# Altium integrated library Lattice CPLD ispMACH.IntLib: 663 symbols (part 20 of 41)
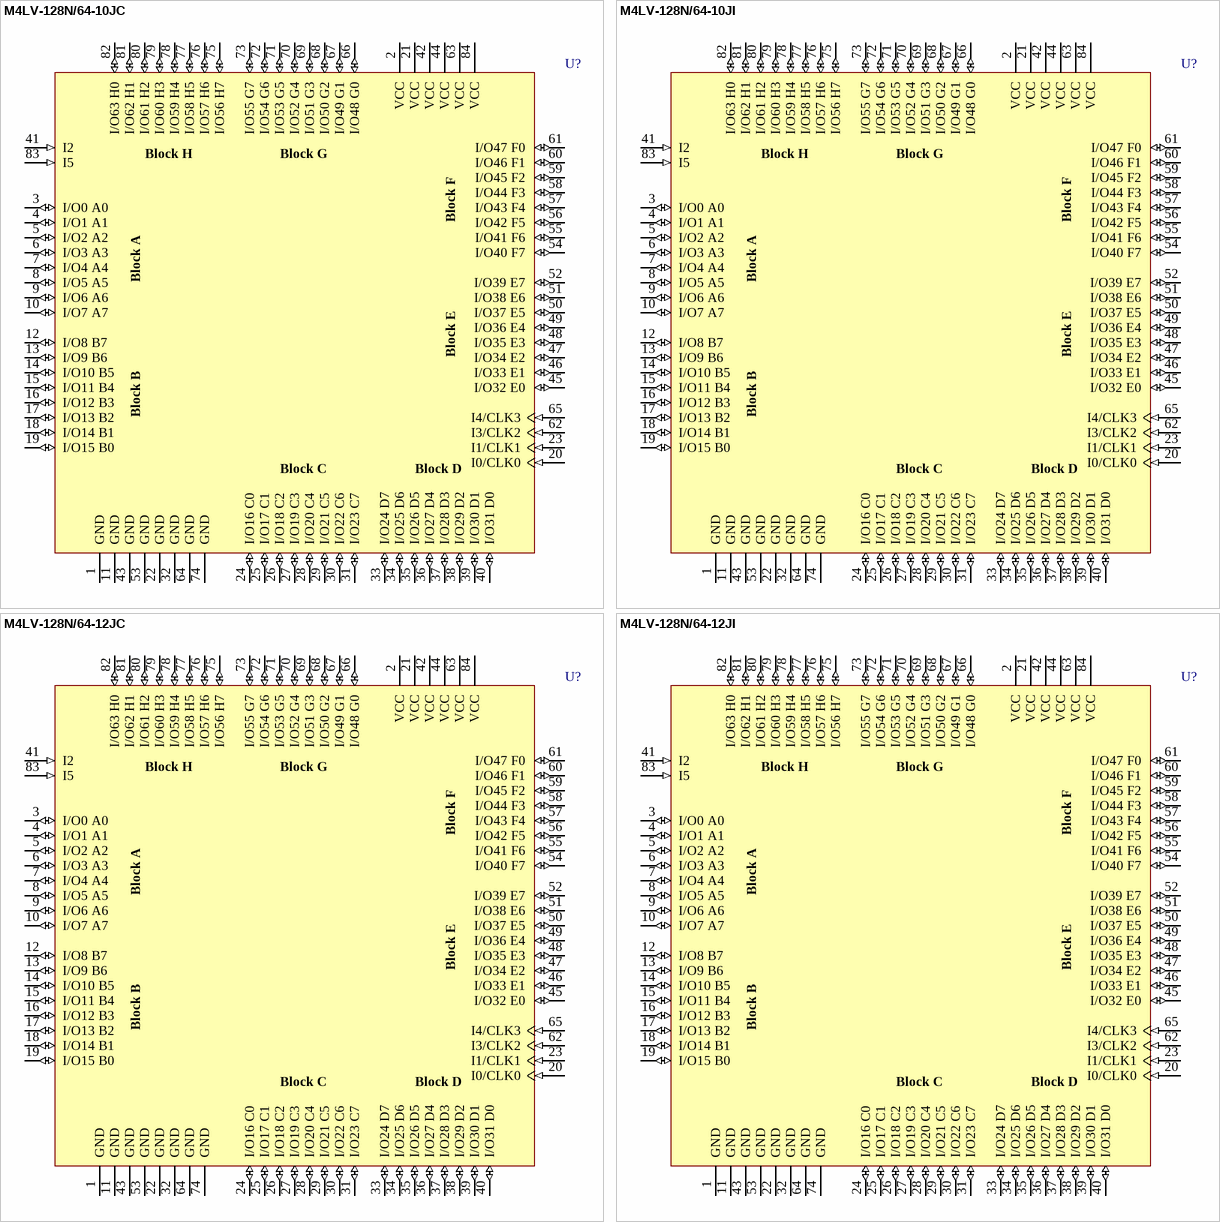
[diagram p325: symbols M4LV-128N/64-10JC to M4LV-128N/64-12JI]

## M4LV-128N/64-10JI
designator U?
High-Performance EE CMOS In-System Programmable Logic
footprint PLCC84_N (Leaded Chip Carrier, 84-Leads, Body 29.3x29.3mm, Pitch 1.27mm, IPC Medium Density)
footprint PLCC84_L (Leaded Chip Carrier, 84-Leads, Body 29.3x29.3mm, Pitch 1.27mm, IPC High Density)
footprint PLCC84_M (Leaded Chip Carrier, 84-Leads, Body 29.3x29.3mm, Pitch 1.27mm, IPC Low Density)
3D model M4LV-PLCC84 (84-Pin Leaded Chip Carrier 1.27 mm Pitch)
pins: 1 GND (power), 2 VCC (power), 3 I/O0 A0 (io), 4 I/O1 A1 (io), 5 I/O2 A2 (io), 6 I/O3 A3 (io), 7 I/O4 A4 (io), 8 I/O5 A5 (io), 9 I/O6 A6 (io), 10 I/O7 A7 (io), 11 GND (power), 12 I/O8 B7 (io), 13 I/O9 B6 (io), 14 I/O10 B5 (io), 15 I/O11 B4 (io), 16 I/O12 B3 (io), 17 I/O13 B2 (io), 18 I/O14 B1 (io), 19 I/O15 B0 (io), 20 I0/CLK0 (in), 21 VCC (power), 22 GND (power), 23 I1/CLK1 (in), 24 I/O16 C0 (io), 25 I/O17 C1 (io), 26 I/O18 C2 (io), 27 I/O19 C3 (io), 28 I/O20 C4 (io), 29 I/O21 C5 (io), 30 I/O22 C6 (io), 31 I/O23 C7 (io), 32 GND (power), 33 I/O24 D7 (io), 34 I/O25 D6 (io), 35 I/O26 D5 (io), 36 I/O27 D4 (io), 37 I/O28 D3 (io), 38 I/O29 D2 (io), 39 I/O30 D1 (io), 40 I/O31 D0 (io), 41 I2 (in), 42 VCC (power), 43 GND (power), 44 VCC (power), 45 I/O32 E0 (io), 46 I/O33 E1 (io), 47 I/O34 E2 (io), 48 I/O35 E3 (io), 49 I/O36 E4 (io), 50 I/O37 E5 (io), 51 I/O38 E6 (io), 52 I/O39 E7 (io), 53 GND (power), 54 I/O40 F7 (io), 55 I/O41 F6 (io), 56 I/O42 F5 (io), 57 I/O43 F4 (io), 58 I/O44 F3 (io), 59 I/O45 F2 (io), 60 I/O46 F1 (io), 61 I/O47 F0 (io), 62 I3/CLK2 (in), 63 VCC (power), 64 GND (power), 65 I4/CLK3 (in), 66 I/O48 G0 (io), 67 I/O49 G1 (io), 68 I/O50 G2 (io), 69 I/O51 G3 (io), 70 I/O52 G4 (io), 71 I/O53 G5 (io), 72 I/O54 G6 (io), 73 I/O55 G7 (io), 74 GND (power), 75 I/O56 H7 (io), 76 I/O57 H6 (io), 77 I/O58 H5 (io), 78 I/O59 H4 (io), 79 I/O60 H3 (io), 80 I/O61 H2 (io), 81 I/O62 H1 (io), 82 I/O63 H0 (io), 83 I5 (in), 84 VCC (power)

## M4LV-128N/64-12JC
designator U?
High-Performance EE CMOS In-System Programmable Logic
footprint PLCC84_N (Leaded Chip Carrier, 84-Leads, Body 29.3x29.3mm, Pitch 1.27mm, IPC Medium Density)
footprint PLCC84_L (Leaded Chip Carrier, 84-Leads, Body 29.3x29.3mm, Pitch 1.27mm, IPC High Density)
footprint PLCC84_M (Leaded Chip Carrier, 84-Leads, Body 29.3x29.3mm, Pitch 1.27mm, IPC Low Density)
3D model M4LV-PLCC84 (84-Pin Leaded Chip Carrier 1.27 mm Pitch)
pins: 1 GND (power), 2 VCC (power), 3 I/O0 A0 (io), 4 I/O1 A1 (io), 5 I/O2 A2 (io), 6 I/O3 A3 (io), 7 I/O4 A4 (io), 8 I/O5 A5 (io), 9 I/O6 A6 (io), 10 I/O7 A7 (io), 11 GND (power), 12 I/O8 B7 (io), 13 I/O9 B6 (io), 14 I/O10 B5 (io), 15 I/O11 B4 (io), 16 I/O12 B3 (io), 17 I/O13 B2 (io), 18 I/O14 B1 (io), 19 I/O15 B0 (io), 20 I0/CLK0 (in), 21 VCC (power), 22 GND (power), 23 I1/CLK1 (in), 24 I/O16 C0 (io), 25 I/O17 C1 (io), 26 I/O18 C2 (io), 27 I/O19 C3 (io), 28 I/O20 C4 (io), 29 I/O21 C5 (io), 30 I/O22 C6 (io), 31 I/O23 C7 (io), 32 GND (power), 33 I/O24 D7 (io), 34 I/O25 D6 (io), 35 I/O26 D5 (io), 36 I/O27 D4 (io), 37 I/O28 D3 (io), 38 I/O29 D2 (io), 39 I/O30 D1 (io), 40 I/O31 D0 (io), 41 I2 (in), 42 VCC (power), 43 GND (power), 44 VCC (power), 45 I/O32 E0 (io), 46 I/O33 E1 (io), 47 I/O34 E2 (io), 48 I/O35 E3 (io), 49 I/O36 E4 (io), 50 I/O37 E5 (io), 51 I/O38 E6 (io), 52 I/O39 E7 (io), 53 GND (power), 54 I/O40 F7 (io), 55 I/O41 F6 (io), 56 I/O42 F5 (io), 57 I/O43 F4 (io), 58 I/O44 F3 (io), 59 I/O45 F2 (io), 60 I/O46 F1 (io), 61 I/O47 F0 (io), 62 I3/CLK2 (in), 63 VCC (power), 64 GND (power), 65 I4/CLK3 (in), 66 I/O48 G0 (io), 67 I/O49 G1 (io), 68 I/O50 G2 (io), 69 I/O51 G3 (io), 70 I/O52 G4 (io), 71 I/O53 G5 (io), 72 I/O54 G6 (io), 73 I/O55 G7 (io), 74 GND (power), 75 I/O56 H7 (io), 76 I/O57 H6 (io), 77 I/O58 H5 (io), 78 I/O59 H4 (io), 79 I/O60 H3 (io), 80 I/O61 H2 (io), 81 I/O62 H1 (io), 82 I/O63 H0 (io), 83 I5 (in), 84 VCC (power)

## M4LV-128N/64-12JI
designator U?
High-Performance EE CMOS In-System Programmable Logic
footprint PLCC84_N (Leaded Chip Carrier, 84-Leads, Body 29.3x29.3mm, Pitch 1.27mm, IPC Medium Density)
footprint PLCC84_L (Leaded Chip Carrier, 84-Leads, Body 29.3x29.3mm, Pitch 1.27mm, IPC High Density)
footprint PLCC84_M (Leaded Chip Carrier, 84-Leads, Body 29.3x29.3mm, Pitch 1.27mm, IPC Low Density)
3D model M4LV-PLCC84 (84-Pin Leaded Chip Carrier 1.27 mm Pitch)
pins: 1 GND (power), 2 VCC (power), 3 I/O0 A0 (io), 4 I/O1 A1 (io), 5 I/O2 A2 (io), 6 I/O3 A3 (io), 7 I/O4 A4 (io), 8 I/O5 A5 (io), 9 I/O6 A6 (io), 10 I/O7 A7 (io), 11 GND (power), 12 I/O8 B7 (io), 13 I/O9 B6 (io), 14 I/O10 B5 (io), 15 I/O11 B4 (io), 16 I/O12 B3 (io), 17 I/O13 B2 (io), 18 I/O14 B1 (io), 19 I/O15 B0 (io), 20 I0/CLK0 (in), 21 VCC (power), 22 GND (power), 23 I1/CLK1 (in), 24 I/O16 C0 (io), 25 I/O17 C1 (io), 26 I/O18 C2 (io), 27 I/O19 C3 (io), 28 I/O20 C4 (io), 29 I/O21 C5 (io), 30 I/O22 C6 (io), 31 I/O23 C7 (io), 32 GND (power), 33 I/O24 D7 (io), 34 I/O25 D6 (io), 35 I/O26 D5 (io), 36 I/O27 D4 (io), 37 I/O28 D3 (io), 38 I/O29 D2 (io), 39 I/O30 D1 (io), 40 I/O31 D0 (io), 41 I2 (in), 42 VCC (power), 43 GND (power), 44 VCC (power), 45 I/O32 E0 (io), 46 I/O33 E1 (io), 47 I/O34 E2 (io), 48 I/O35 E3 (io), 49 I/O36 E4 (io), 50 I/O37 E5 (io), 51 I/O38 E6 (io), 52 I/O39 E7 (io), 53 GND (power), 54 I/O40 F7 (io), 55 I/O41 F6 (io), 56 I/O42 F5 (io), 57 I/O43 F4 (io), 58 I/O44 F3 (io), 59 I/O45 F2 (io), 60 I/O46 F1 (io), 61 I/O47 F0 (io), 62 I3/CLK2 (in), 63 VCC (power), 64 GND (power), 65 I4/CLK3 (in), 66 I/O48 G0 (io), 67 I/O49 G1 (io), 68 I/O50 G2 (io), 69 I/O51 G3 (io), 70 I/O52 G4 (io), 71 I/O53 G5 (io), 72 I/O54 G6 (io), 73 I/O55 G7 (io), 74 GND (power), 75 I/O56 H7 (io), 76 I/O57 H6 (io), 77 I/O58 H5 (io), 78 I/O59 H4 (io), 79 I/O60 H3 (io), 80 I/O61 H2 (io), 81 I/O62 H1 (io), 82 I/O63 H0 (io), 83 I5 (in), 84 VCC (power)

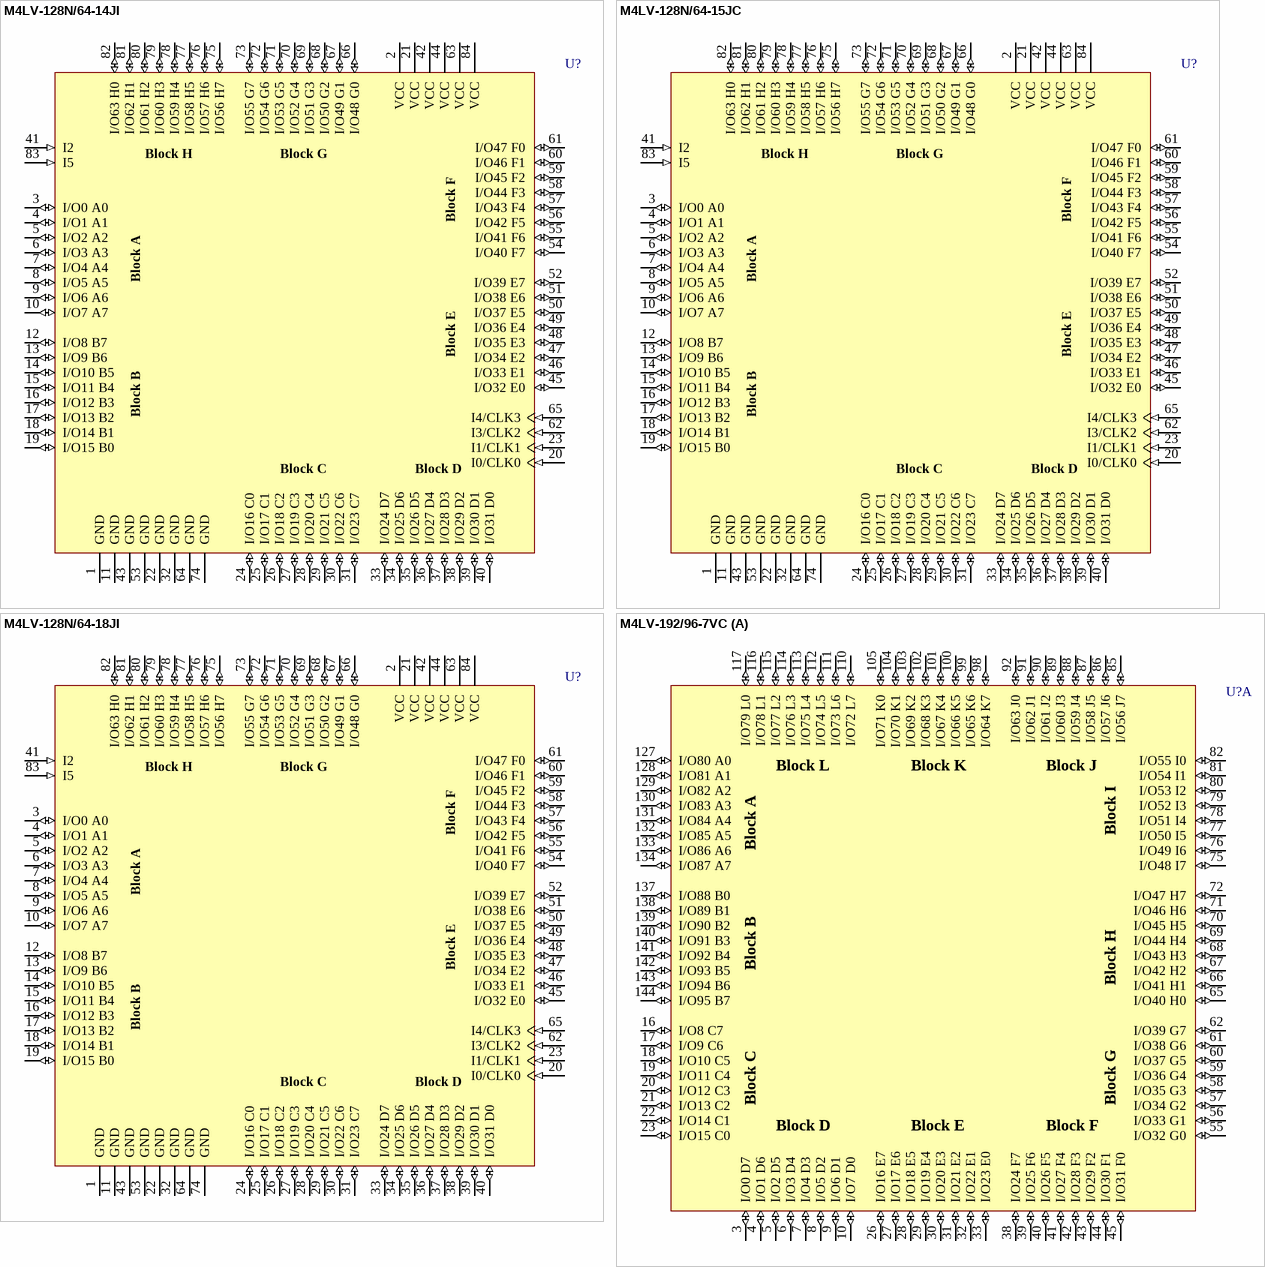
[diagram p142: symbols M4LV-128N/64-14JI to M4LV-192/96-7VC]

## M4LV-128N/64-14JI
designator U?
High-Performance EE CMOS In-System Programmable Logic
footprint PLCC84_N (Leaded Chip Carrier, 84-Leads, Body 29.3x29.3mm, Pitch 1.27mm, IPC Medium Density)
footprint PLCC84_L (Leaded Chip Carrier, 84-Leads, Body 29.3x29.3mm, Pitch 1.27mm, IPC High Density)
footprint PLCC84_M (Leaded Chip Carrier, 84-Leads, Body 29.3x29.3mm, Pitch 1.27mm, IPC Low Density)
3D model M4LV-PLCC84 (84-Pin Leaded Chip Carrier 1.27 mm Pitch)
pins: 1 GND (power), 2 VCC (power), 3 I/O0 A0 (io), 4 I/O1 A1 (io), 5 I/O2 A2 (io), 6 I/O3 A3 (io), 7 I/O4 A4 (io), 8 I/O5 A5 (io), 9 I/O6 A6 (io), 10 I/O7 A7 (io), 11 GND (power), 12 I/O8 B7 (io), 13 I/O9 B6 (io), 14 I/O10 B5 (io), 15 I/O11 B4 (io), 16 I/O12 B3 (io), 17 I/O13 B2 (io), 18 I/O14 B1 (io), 19 I/O15 B0 (io), 20 I0/CLK0 (in), 21 VCC (power), 22 GND (power), 23 I1/CLK1 (in), 24 I/O16 C0 (io), 25 I/O17 C1 (io), 26 I/O18 C2 (io), 27 I/O19 C3 (io), 28 I/O20 C4 (io), 29 I/O21 C5 (io), 30 I/O22 C6 (io), 31 I/O23 C7 (io), 32 GND (power), 33 I/O24 D7 (io), 34 I/O25 D6 (io), 35 I/O26 D5 (io), 36 I/O27 D4 (io), 37 I/O28 D3 (io), 38 I/O29 D2 (io), 39 I/O30 D1 (io), 40 I/O31 D0 (io), 41 I2 (in), 42 VCC (power), 43 GND (power), 44 VCC (power), 45 I/O32 E0 (io), 46 I/O33 E1 (io), 47 I/O34 E2 (io), 48 I/O35 E3 (io), 49 I/O36 E4 (io), 50 I/O37 E5 (io), 51 I/O38 E6 (io), 52 I/O39 E7 (io), 53 GND (power), 54 I/O40 F7 (io), 55 I/O41 F6 (io), 56 I/O42 F5 (io), 57 I/O43 F4 (io), 58 I/O44 F3 (io), 59 I/O45 F2 (io), 60 I/O46 F1 (io), 61 I/O47 F0 (io), 62 I3/CLK2 (in), 63 VCC (power), 64 GND (power), 65 I4/CLK3 (in), 66 I/O48 G0 (io), 67 I/O49 G1 (io), 68 I/O50 G2 (io), 69 I/O51 G3 (io), 70 I/O52 G4 (io), 71 I/O53 G5 (io), 72 I/O54 G6 (io), 73 I/O55 G7 (io), 74 GND (power), 75 I/O56 H7 (io), 76 I/O57 H6 (io), 77 I/O58 H5 (io), 78 I/O59 H4 (io), 79 I/O60 H3 (io), 80 I/O61 H2 (io), 81 I/O62 H1 (io), 82 I/O63 H0 (io), 83 I5 (in), 84 VCC (power)

## M4LV-128N/64-15JC
designator U?
High-Performance EE CMOS In-System Programmable Logic
footprint PLCC84_N (Leaded Chip Carrier, 84-Leads, Body 29.3x29.3mm, Pitch 1.27mm, IPC Medium Density)
footprint PLCC84_L (Leaded Chip Carrier, 84-Leads, Body 29.3x29.3mm, Pitch 1.27mm, IPC High Density)
footprint PLCC84_M (Leaded Chip Carrier, 84-Leads, Body 29.3x29.3mm, Pitch 1.27mm, IPC Low Density)
3D model M4LV-PLCC84 (84-Pin Leaded Chip Carrier 1.27 mm Pitch)
pins: 1 GND (power), 2 VCC (power), 3 I/O0 A0 (io), 4 I/O1 A1 (io), 5 I/O2 A2 (io), 6 I/O3 A3 (io), 7 I/O4 A4 (io), 8 I/O5 A5 (io), 9 I/O6 A6 (io), 10 I/O7 A7 (io), 11 GND (power), 12 I/O8 B7 (io), 13 I/O9 B6 (io), 14 I/O10 B5 (io), 15 I/O11 B4 (io), 16 I/O12 B3 (io), 17 I/O13 B2 (io), 18 I/O14 B1 (io), 19 I/O15 B0 (io), 20 I0/CLK0 (in), 21 VCC (power), 22 GND (power), 23 I1/CLK1 (in), 24 I/O16 C0 (io), 25 I/O17 C1 (io), 26 I/O18 C2 (io), 27 I/O19 C3 (io), 28 I/O20 C4 (io), 29 I/O21 C5 (io), 30 I/O22 C6 (io), 31 I/O23 C7 (io), 32 GND (power), 33 I/O24 D7 (io), 34 I/O25 D6 (io), 35 I/O26 D5 (io), 36 I/O27 D4 (io), 37 I/O28 D3 (io), 38 I/O29 D2 (io), 39 I/O30 D1 (io), 40 I/O31 D0 (io), 41 I2 (in), 42 VCC (power), 43 GND (power), 44 VCC (power), 45 I/O32 E0 (io), 46 I/O33 E1 (io), 47 I/O34 E2 (io), 48 I/O35 E3 (io), 49 I/O36 E4 (io), 50 I/O37 E5 (io), 51 I/O38 E6 (io), 52 I/O39 E7 (io), 53 GND (power), 54 I/O40 F7 (io), 55 I/O41 F6 (io), 56 I/O42 F5 (io), 57 I/O43 F4 (io), 58 I/O44 F3 (io), 59 I/O45 F2 (io), 60 I/O46 F1 (io), 61 I/O47 F0 (io), 62 I3/CLK2 (in), 63 VCC (power), 64 GND (power), 65 I4/CLK3 (in), 66 I/O48 G0 (io), 67 I/O49 G1 (io), 68 I/O50 G2 (io), 69 I/O51 G3 (io), 70 I/O52 G4 (io), 71 I/O53 G5 (io), 72 I/O54 G6 (io), 73 I/O55 G7 (io), 74 GND (power), 75 I/O56 H7 (io), 76 I/O57 H6 (io), 77 I/O58 H5 (io), 78 I/O59 H4 (io), 79 I/O60 H3 (io), 80 I/O61 H2 (io), 81 I/O62 H1 (io), 82 I/O63 H0 (io), 83 I5 (in), 84 VCC (power)

## M4LV-128N/64-18JI
designator U?
High-Performance EE CMOS In-System Programmable Logic
footprint PLCC84_N (Leaded Chip Carrier, 84-Leads, Body 29.3x29.3mm, Pitch 1.27mm, IPC Medium Density)
footprint PLCC84_L (Leaded Chip Carrier, 84-Leads, Body 29.3x29.3mm, Pitch 1.27mm, IPC High Density)
footprint PLCC84_M (Leaded Chip Carrier, 84-Leads, Body 29.3x29.3mm, Pitch 1.27mm, IPC Low Density)
3D model M4LV-PLCC84 (84-Pin Leaded Chip Carrier 1.27 mm Pitch)
pins: 1 GND (power), 2 VCC (power), 3 I/O0 A0 (io), 4 I/O1 A1 (io), 5 I/O2 A2 (io), 6 I/O3 A3 (io), 7 I/O4 A4 (io), 8 I/O5 A5 (io), 9 I/O6 A6 (io), 10 I/O7 A7 (io), 11 GND (power), 12 I/O8 B7 (io), 13 I/O9 B6 (io), 14 I/O10 B5 (io), 15 I/O11 B4 (io), 16 I/O12 B3 (io), 17 I/O13 B2 (io), 18 I/O14 B1 (io), 19 I/O15 B0 (io), 20 I0/CLK0 (in), 21 VCC (power), 22 GND (power), 23 I1/CLK1 (in), 24 I/O16 C0 (io), 25 I/O17 C1 (io), 26 I/O18 C2 (io), 27 I/O19 C3 (io), 28 I/O20 C4 (io), 29 I/O21 C5 (io), 30 I/O22 C6 (io), 31 I/O23 C7 (io), 32 GND (power), 33 I/O24 D7 (io), 34 I/O25 D6 (io), 35 I/O26 D5 (io), 36 I/O27 D4 (io), 37 I/O28 D3 (io), 38 I/O29 D2 (io), 39 I/O30 D1 (io), 40 I/O31 D0 (io), 41 I2 (in), 42 VCC (power), 43 GND (power), 44 VCC (power), 45 I/O32 E0 (io), 46 I/O33 E1 (io), 47 I/O34 E2 (io), 48 I/O35 E3 (io), 49 I/O36 E4 (io), 50 I/O37 E5 (io), 51 I/O38 E6 (io), 52 I/O39 E7 (io), 53 GND (power), 54 I/O40 F7 (io), 55 I/O41 F6 (io), 56 I/O42 F5 (io), 57 I/O43 F4 (io), 58 I/O44 F3 (io), 59 I/O45 F2 (io), 60 I/O46 F1 (io), 61 I/O47 F0 (io), 62 I3/CLK2 (in), 63 VCC (power), 64 GND (power), 65 I4/CLK3 (in), 66 I/O48 G0 (io), 67 I/O49 G1 (io), 68 I/O50 G2 (io), 69 I/O51 G3 (io), 70 I/O52 G4 (io), 71 I/O53 G5 (io), 72 I/O54 G6 (io), 73 I/O55 G7 (io), 74 GND (power), 75 I/O56 H7 (io), 76 I/O57 H6 (io), 77 I/O58 H5 (io), 78 I/O59 H4 (io), 79 I/O60 H3 (io), 80 I/O61 H2 (io), 81 I/O62 H1 (io), 82 I/O63 H0 (io), 83 I5 (in), 84 VCC (power)

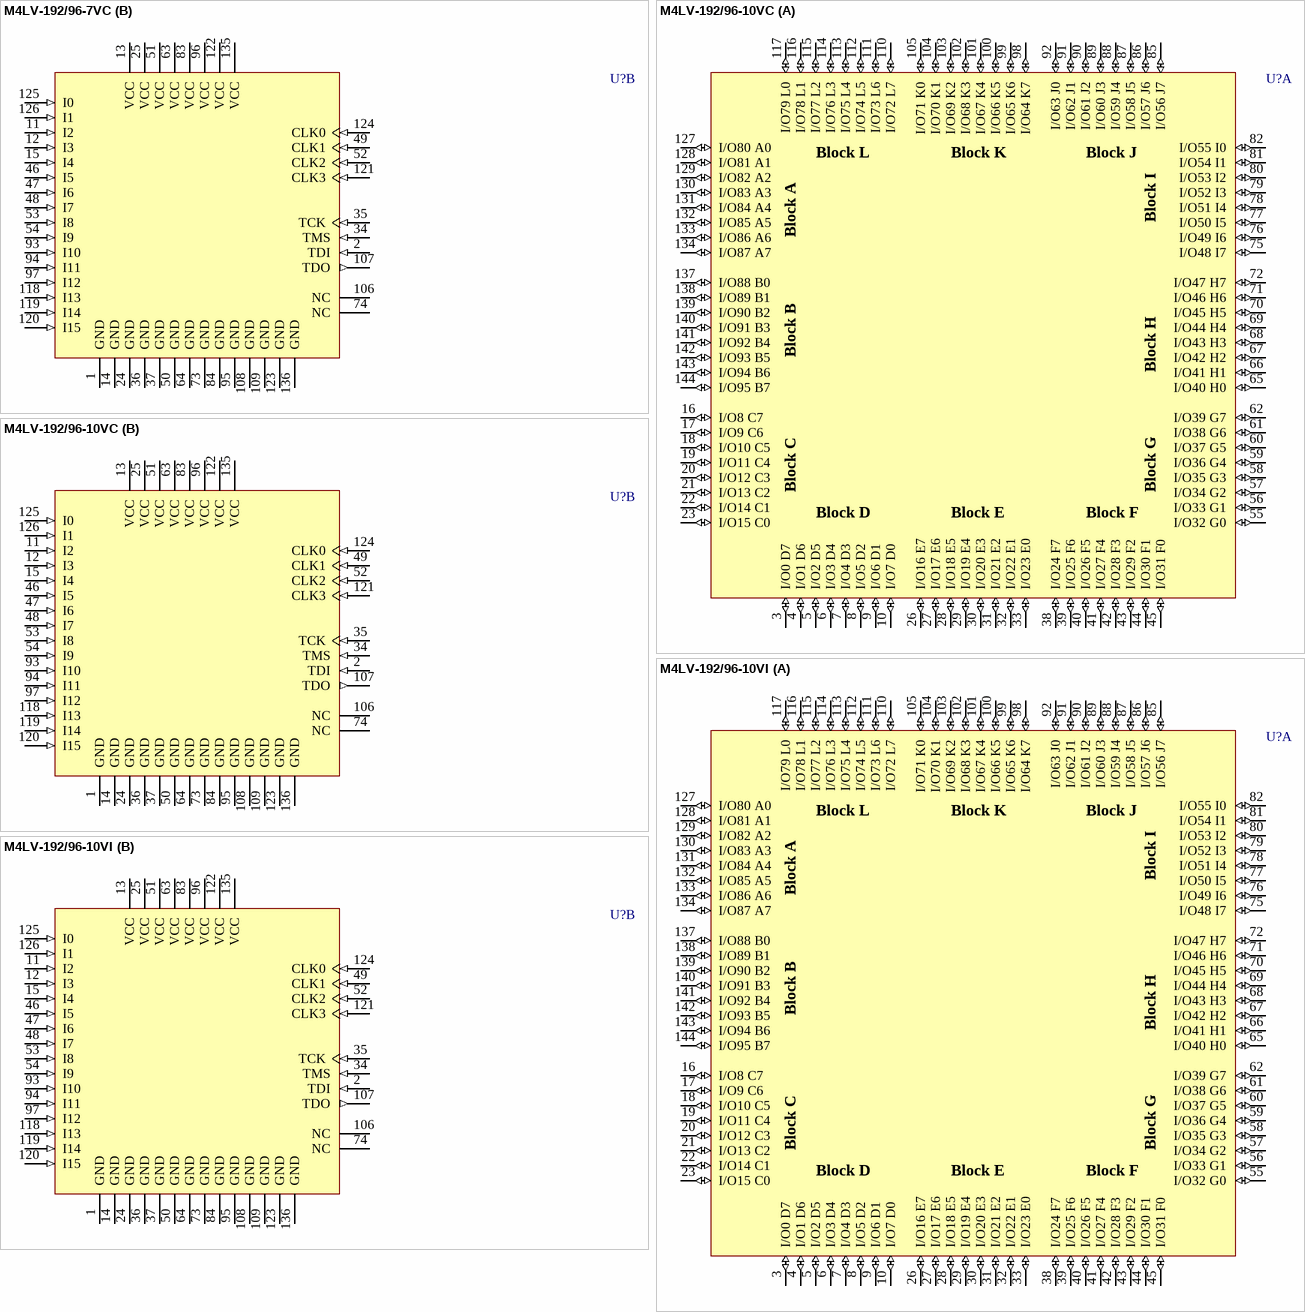
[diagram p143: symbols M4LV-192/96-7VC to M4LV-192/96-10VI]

## M4LV-192/96-7VC
designator U?
High-Performance EE CMOS In-System Programmable Logic
footprint TQFP144_N (Thin QFP, 144-Leads, Body 20x20mm, Pitch 0.5mm, IPC Medium Density)
footprint TQFP144_L (Thin QFP, 144-Leads, Body 20x20mm, Pitch 0.5mm, IPC High Density)
footprint TQFP144_M (Thin QFP, 144-Leads, Body 20x20mm, Pitch 0.5mm, IPC Low Density)
3D model M4LV-TQFP144 (144-Pin Thin Quad Flat Pack (TQFP144))
part A pins: 3 I/O0 D7 (io), 4 I/O1 D6 (io), 5 I/O2 D5 (io), 6 I/O3 D4 (io), 7 I/O4 D3 (io), 8 I/O5 D2 (io), 9 I/O6 D1 (io), 10 I/O7 D0 (io), 16 I/O8 C7 (io), 17 I/O9 C6 (io), 18 I/O10 C5 (io), 19 I/O11 C4 (io), 20 I/O12 C3 (io), 21 I/O13 C2 (io), 22 I/O14 C1 (io), 23 I/O15 C0 (io), 26 I/O16 E7 (io), 27 I/O17 E6 (io), 28 I/O18 E5 (io), 29 I/O19 E4 (io), 30 I/O20 E3 (io), 31 I/O21 E2 (io), 32 I/O22 E1 (io), 33 I/O23 E0 (io), 38 I/O24 F7 (io), 39 I/O25 F6 (io), 40 I/O26 F5 (io), 41 I/O27 F4 (io), 42 I/O28 F3 (io), 43 I/O29 F2 (io), 44 I/O30 F1 (io), 45 I/O31 F0 (io), 55 I/O32 G0 (io), 56 I/O33 G1 (io), 57 I/O34 G2 (io), 58 I/O35 G3 (io), 59 I/O36 G4 (io), 60 I/O37 G5 (io), 61 I/O38 G6 (io), 62 I/O39 G7 (io), 65 I/O40 H0 (io), 66 I/O41 H1 (io), 67 I/O42 H2 (io), 68 I/O43 H3 (io), 69 I/O44 H4 (io), 70 I/O45 H5 (io), 71 I/O46 H6 (io), 72 I/O47 H7 (io), 75 I/O48 I7 (io), 76 I/O49 I6 (io), 77 I/O50 I5 (io), 78 I/O51 I4 (io), 79 I/O52 I3 (io), 80 I/O53 I2 (io), 81 I/O54 I1 (io), 82 I/O55 I0 (io), 85 I/O56 J7 (io), 86 I/O57 J6 (io), 87 I/O58 J5 (io), 88 I/O59 J4 (io), 89 I/O60 J3 (io), 90 I/O61 J2 (io), 91 I/O62 J1 (io), 92 I/O63 J0 (io), 98 I/O64 K7 (io), 99 I/O65 K6 (io), 100 I/O66 K5 (io), 101 I/O67 K4 (io), 102 I/O68 K3 (io), 103 I/O69 K2 (io), 104 I/O70 K1 (io), 105 I/O71 K0 (io), 110 I/O72 L7 (io), 111 I/O73 L6 (io), 112 I/O74 L5 (io), 113 I/O75 L4 (io), 114 I/O76 L3 (io), 115 I/O77 L2 (io), 116 I/O78 L1 (io), 117 I/O79 L0 (io), 127 I/O80 A0 (io), 128 I/O81 A1 (io), 129 I/O82 A2 (io), 130 I/O83 A3 (io), 131 I/O84 A4 (io), 132 I/O85 A5 (io), 133 I/O86 A6 (io), 134 I/O87 A7 (io), 137 I/O88 B0 (io), 138 I/O89 B1 (io), 139 I/O90 B2 (io), 140 I/O91 B3 (io), 141 I/O92 B4 (io), 142 I/O93 B5 (io), 143 I/O94 B6 (io), 144 I/O95 B7 (io)
part B pins: 1 GND (power), 2 TDI (in), 11 I2 (in), 12 I3 (in), 13 VCC (power), 14 GND (power), 15 I4 (in), 24 GND (power), 25 VCC (power), 34 TMS (in), 35 TCK (in), 36 GND (power), 37 GND (power), 46 I5 (in), 47 I6 (in), 48 I7 (in), 49 CLK1 (in), 50 GND (power), 51 VCC (power), 52 CLK2 (in), 53 I8 (in), 54 I9 (in), 63 VCC (power), 64 GND (power), 73 GND (power), 74 NC, 83 VCC (power), 84 GND (power), 93 I10 (in), 94 I11 (in), 95 GND (power), 96 VCC (power), 97 I12 (in), 106 NC, 107 TDO (out), 108 GND (power), 109 GND (power), 118 I13 (in), 119 I14 (in), 120 I15 (in), 121 CLK3 (in), 122 VCC (power), 123 GND (power), 124 CLK0 (in), 125 I0 (in), 126 I1 (in), 135 VCC (power), 136 GND (power)

## M4LV-192/96-10VC
designator U?
High-Performance EE CMOS In-System Programmable Logic
footprint TQFP144_N (Thin QFP, 144-Leads, Body 20x20mm, Pitch 0.5mm, IPC Medium Density)
footprint TQFP144_L (Thin QFP, 144-Leads, Body 20x20mm, Pitch 0.5mm, IPC High Density)
footprint TQFP144_M (Thin QFP, 144-Leads, Body 20x20mm, Pitch 0.5mm, IPC Low Density)
3D model M4LV-TQFP144 (144-Pin Thin Quad Flat Pack (TQFP144))
part A pins: 3 I/O0 D7 (io), 4 I/O1 D6 (io), 5 I/O2 D5 (io), 6 I/O3 D4 (io), 7 I/O4 D3 (io), 8 I/O5 D2 (io), 9 I/O6 D1 (io), 10 I/O7 D0 (io), 16 I/O8 C7 (io), 17 I/O9 C6 (io), 18 I/O10 C5 (io), 19 I/O11 C4 (io), 20 I/O12 C3 (io), 21 I/O13 C2 (io), 22 I/O14 C1 (io), 23 I/O15 C0 (io), 26 I/O16 E7 (io), 27 I/O17 E6 (io), 28 I/O18 E5 (io), 29 I/O19 E4 (io), 30 I/O20 E3 (io), 31 I/O21 E2 (io), 32 I/O22 E1 (io), 33 I/O23 E0 (io), 38 I/O24 F7 (io), 39 I/O25 F6 (io), 40 I/O26 F5 (io), 41 I/O27 F4 (io), 42 I/O28 F3 (io), 43 I/O29 F2 (io), 44 I/O30 F1 (io), 45 I/O31 F0 (io), 55 I/O32 G0 (io), 56 I/O33 G1 (io), 57 I/O34 G2 (io), 58 I/O35 G3 (io), 59 I/O36 G4 (io), 60 I/O37 G5 (io), 61 I/O38 G6 (io), 62 I/O39 G7 (io), 65 I/O40 H0 (io), 66 I/O41 H1 (io), 67 I/O42 H2 (io), 68 I/O43 H3 (io), 69 I/O44 H4 (io), 70 I/O45 H5 (io), 71 I/O46 H6 (io), 72 I/O47 H7 (io), 75 I/O48 I7 (io), 76 I/O49 I6 (io), 77 I/O50 I5 (io), 78 I/O51 I4 (io), 79 I/O52 I3 (io), 80 I/O53 I2 (io), 81 I/O54 I1 (io), 82 I/O55 I0 (io), 85 I/O56 J7 (io), 86 I/O57 J6 (io), 87 I/O58 J5 (io), 88 I/O59 J4 (io), 89 I/O60 J3 (io), 90 I/O61 J2 (io), 91 I/O62 J1 (io), 92 I/O63 J0 (io), 98 I/O64 K7 (io), 99 I/O65 K6 (io), 100 I/O66 K5 (io), 101 I/O67 K4 (io), 102 I/O68 K3 (io), 103 I/O69 K2 (io), 104 I/O70 K1 (io), 105 I/O71 K0 (io), 110 I/O72 L7 (io), 111 I/O73 L6 (io), 112 I/O74 L5 (io), 113 I/O75 L4 (io), 114 I/O76 L3 (io), 115 I/O77 L2 (io), 116 I/O78 L1 (io), 117 I/O79 L0 (io), 127 I/O80 A0 (io), 128 I/O81 A1 (io), 129 I/O82 A2 (io), 130 I/O83 A3 (io), 131 I/O84 A4 (io), 132 I/O85 A5 (io), 133 I/O86 A6 (io), 134 I/O87 A7 (io), 137 I/O88 B0 (io), 138 I/O89 B1 (io), 139 I/O90 B2 (io), 140 I/O91 B3 (io), 141 I/O92 B4 (io), 142 I/O93 B5 (io), 143 I/O94 B6 (io), 144 I/O95 B7 (io)
part B pins: 1 GND (power), 2 TDI (in), 11 I2 (in), 12 I3 (in), 13 VCC (power), 14 GND (power), 15 I4 (in), 24 GND (power), 25 VCC (power), 34 TMS (in), 35 TCK (in), 36 GND (power), 37 GND (power), 46 I5 (in), 47 I6 (in), 48 I7 (in), 49 CLK1 (in), 50 GND (power), 51 VCC (power), 52 CLK2 (in), 53 I8 (in), 54 I9 (in), 63 VCC (power), 64 GND (power), 73 GND (power), 74 NC, 83 VCC (power), 84 GND (power), 93 I10 (in), 94 I11 (in), 95 GND (power), 96 VCC (power), 97 I12 (in), 106 NC, 107 TDO (out), 108 GND (power), 109 GND (power), 118 I13 (in), 119 I14 (in), 120 I15 (in), 121 CLK3 (in), 122 VCC (power), 123 GND (power), 124 CLK0 (in), 125 I0 (in), 126 I1 (in), 135 VCC (power), 136 GND (power)

## M4LV-192/96-10VI
designator U?
High-Performance EE CMOS In-System Programmable Logic
footprint TQFP144_N (Thin QFP, 144-Leads, Body 20x20mm, Pitch 0.5mm, IPC Medium Density)
footprint TQFP144_L (Thin QFP, 144-Leads, Body 20x20mm, Pitch 0.5mm, IPC High Density)
footprint TQFP144_M (Thin QFP, 144-Leads, Body 20x20mm, Pitch 0.5mm, IPC Low Density)
3D model M4LV-TQFP144 (144-Pin Thin Quad Flat Pack (TQFP144))
part A pins: 3 I/O0 D7 (io), 4 I/O1 D6 (io), 5 I/O2 D5 (io), 6 I/O3 D4 (io), 7 I/O4 D3 (io), 8 I/O5 D2 (io), 9 I/O6 D1 (io), 10 I/O7 D0 (io), 16 I/O8 C7 (io), 17 I/O9 C6 (io), 18 I/O10 C5 (io), 19 I/O11 C4 (io), 20 I/O12 C3 (io), 21 I/O13 C2 (io), 22 I/O14 C1 (io), 23 I/O15 C0 (io), 26 I/O16 E7 (io), 27 I/O17 E6 (io), 28 I/O18 E5 (io), 29 I/O19 E4 (io), 30 I/O20 E3 (io), 31 I/O21 E2 (io), 32 I/O22 E1 (io), 33 I/O23 E0 (io), 38 I/O24 F7 (io), 39 I/O25 F6 (io), 40 I/O26 F5 (io), 41 I/O27 F4 (io), 42 I/O28 F3 (io), 43 I/O29 F2 (io), 44 I/O30 F1 (io), 45 I/O31 F0 (io), 55 I/O32 G0 (io), 56 I/O33 G1 (io), 57 I/O34 G2 (io), 58 I/O35 G3 (io), 59 I/O36 G4 (io), 60 I/O37 G5 (io), 61 I/O38 G6 (io), 62 I/O39 G7 (io), 65 I/O40 H0 (io), 66 I/O41 H1 (io), 67 I/O42 H2 (io), 68 I/O43 H3 (io), 69 I/O44 H4 (io), 70 I/O45 H5 (io), 71 I/O46 H6 (io), 72 I/O47 H7 (io), 75 I/O48 I7 (io), 76 I/O49 I6 (io), 77 I/O50 I5 (io), 78 I/O51 I4 (io), 79 I/O52 I3 (io), 80 I/O53 I2 (io), 81 I/O54 I1 (io), 82 I/O55 I0 (io), 85 I/O56 J7 (io), 86 I/O57 J6 (io), 87 I/O58 J5 (io), 88 I/O59 J4 (io), 89 I/O60 J3 (io), 90 I/O61 J2 (io), 91 I/O62 J1 (io), 92 I/O63 J0 (io), 98 I/O64 K7 (io), 99 I/O65 K6 (io), 100 I/O66 K5 (io), 101 I/O67 K4 (io), 102 I/O68 K3 (io), 103 I/O69 K2 (io), 104 I/O70 K1 (io), 105 I/O71 K0 (io), 110 I/O72 L7 (io), 111 I/O73 L6 (io), 112 I/O74 L5 (io), 113 I/O75 L4 (io), 114 I/O76 L3 (io), 115 I/O77 L2 (io), 116 I/O78 L1 (io), 117 I/O79 L0 (io), 127 I/O80 A0 (io), 128 I/O81 A1 (io), 129 I/O82 A2 (io), 130 I/O83 A3 (io), 131 I/O84 A4 (io), 132 I/O85 A5 (io), 133 I/O86 A6 (io), 134 I/O87 A7 (io), 137 I/O88 B0 (io), 138 I/O89 B1 (io), 139 I/O90 B2 (io), 140 I/O91 B3 (io), 141 I/O92 B4 (io), 142 I/O93 B5 (io), 143 I/O94 B6 (io), 144 I/O95 B7 (io)
part B pins: 1 GND (power), 2 TDI (in), 11 I2 (in), 12 I3 (in), 13 VCC (power), 14 GND (power), 15 I4 (in), 24 GND (power), 25 VCC (power), 34 TMS (in), 35 TCK (in), 36 GND (power), 37 GND (power), 46 I5 (in), 47 I6 (in), 48 I7 (in), 49 CLK1 (in), 50 GND (power), 51 VCC (power), 52 CLK2 (in), 53 I8 (in), 54 I9 (in), 63 VCC (power), 64 GND (power), 73 GND (power), 74 NC, 83 VCC (power), 84 GND (power), 93 I10 (in), 94 I11 (in), 95 GND (power), 96 VCC (power), 97 I12 (in), 106 NC, 107 TDO (out), 108 GND (power), 109 GND (power), 118 I13 (in), 119 I14 (in), 120 I15 (in), 121 CLK3 (in), 122 VCC (power), 123 GND (power), 124 CLK0 (in), 125 I0 (in), 126 I1 (in), 135 VCC (power), 136 GND (power)

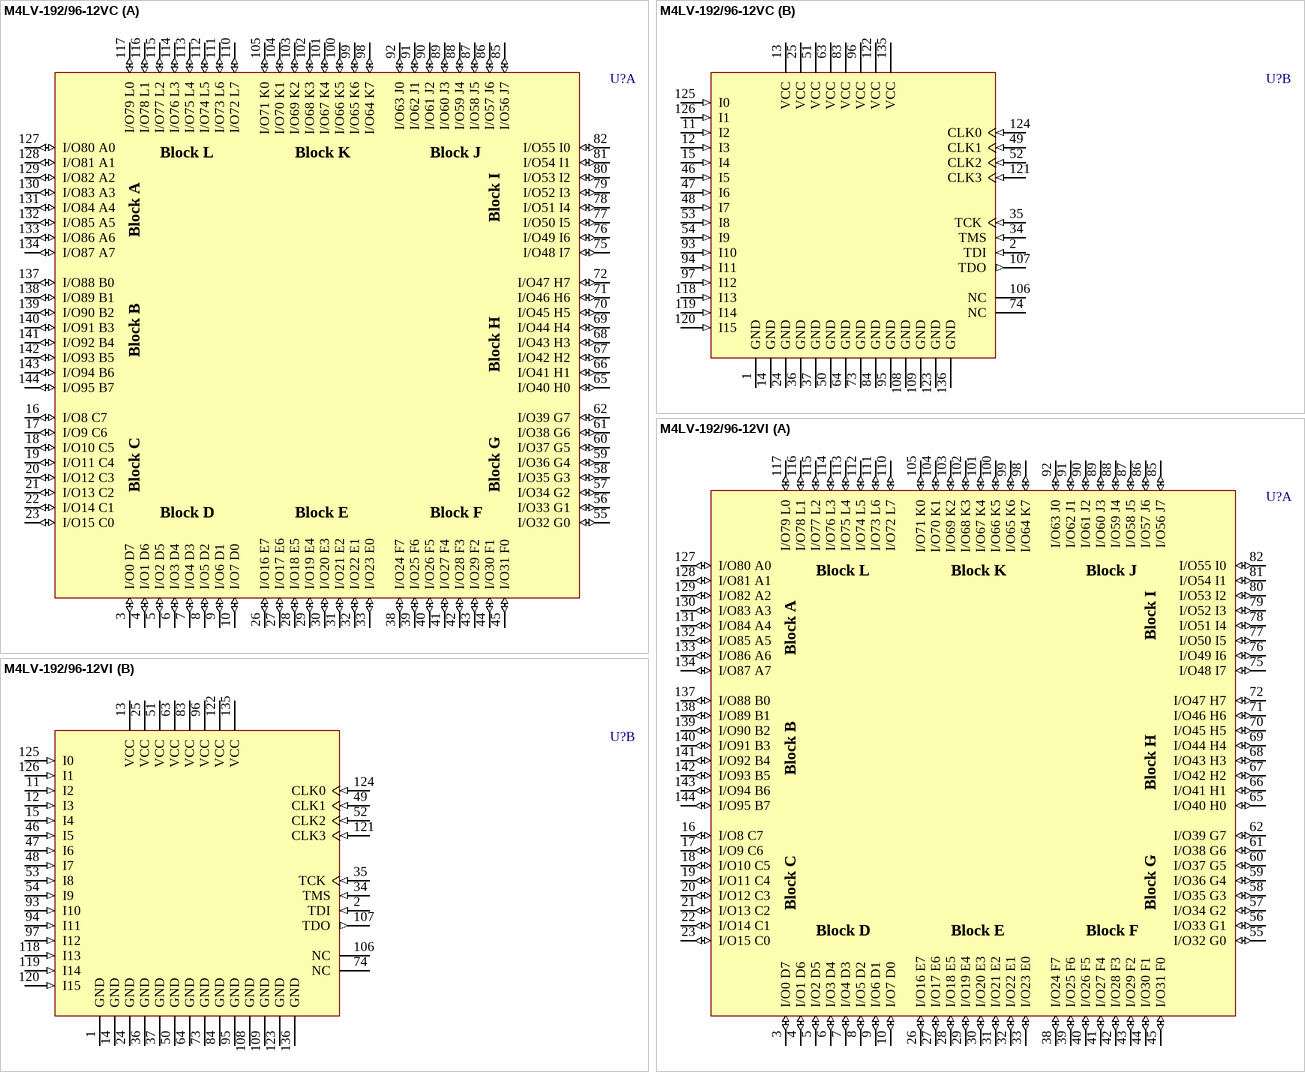
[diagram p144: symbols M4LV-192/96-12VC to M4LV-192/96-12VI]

## M4LV-192/96-12VC
designator U?
High-Performance EE CMOS In-System Programmable Logic
footprint TQFP144_N (Thin QFP, 144-Leads, Body 20x20mm, Pitch 0.5mm, IPC Medium Density)
footprint TQFP144_L (Thin QFP, 144-Leads, Body 20x20mm, Pitch 0.5mm, IPC High Density)
footprint TQFP144_M (Thin QFP, 144-Leads, Body 20x20mm, Pitch 0.5mm, IPC Low Density)
3D model M4LV-TQFP144 (144-Pin Thin Quad Flat Pack (TQFP144))
part A pins: 3 I/O0 D7 (io), 4 I/O1 D6 (io), 5 I/O2 D5 (io), 6 I/O3 D4 (io), 7 I/O4 D3 (io), 8 I/O5 D2 (io), 9 I/O6 D1 (io), 10 I/O7 D0 (io), 16 I/O8 C7 (io), 17 I/O9 C6 (io), 18 I/O10 C5 (io), 19 I/O11 C4 (io), 20 I/O12 C3 (io), 21 I/O13 C2 (io), 22 I/O14 C1 (io), 23 I/O15 C0 (io), 26 I/O16 E7 (io), 27 I/O17 E6 (io), 28 I/O18 E5 (io), 29 I/O19 E4 (io), 30 I/O20 E3 (io), 31 I/O21 E2 (io), 32 I/O22 E1 (io), 33 I/O23 E0 (io), 38 I/O24 F7 (io), 39 I/O25 F6 (io), 40 I/O26 F5 (io), 41 I/O27 F4 (io), 42 I/O28 F3 (io), 43 I/O29 F2 (io), 44 I/O30 F1 (io), 45 I/O31 F0 (io), 55 I/O32 G0 (io), 56 I/O33 G1 (io), 57 I/O34 G2 (io), 58 I/O35 G3 (io), 59 I/O36 G4 (io), 60 I/O37 G5 (io), 61 I/O38 G6 (io), 62 I/O39 G7 (io), 65 I/O40 H0 (io), 66 I/O41 H1 (io), 67 I/O42 H2 (io), 68 I/O43 H3 (io), 69 I/O44 H4 (io), 70 I/O45 H5 (io), 71 I/O46 H6 (io), 72 I/O47 H7 (io), 75 I/O48 I7 (io), 76 I/O49 I6 (io), 77 I/O50 I5 (io), 78 I/O51 I4 (io), 79 I/O52 I3 (io), 80 I/O53 I2 (io), 81 I/O54 I1 (io), 82 I/O55 I0 (io), 85 I/O56 J7 (io), 86 I/O57 J6 (io), 87 I/O58 J5 (io), 88 I/O59 J4 (io), 89 I/O60 J3 (io), 90 I/O61 J2 (io), 91 I/O62 J1 (io), 92 I/O63 J0 (io), 98 I/O64 K7 (io), 99 I/O65 K6 (io), 100 I/O66 K5 (io), 101 I/O67 K4 (io), 102 I/O68 K3 (io), 103 I/O69 K2 (io), 104 I/O70 K1 (io), 105 I/O71 K0 (io), 110 I/O72 L7 (io), 111 I/O73 L6 (io), 112 I/O74 L5 (io), 113 I/O75 L4 (io), 114 I/O76 L3 (io), 115 I/O77 L2 (io), 116 I/O78 L1 (io), 117 I/O79 L0 (io), 127 I/O80 A0 (io), 128 I/O81 A1 (io), 129 I/O82 A2 (io), 130 I/O83 A3 (io), 131 I/O84 A4 (io), 132 I/O85 A5 (io), 133 I/O86 A6 (io), 134 I/O87 A7 (io), 137 I/O88 B0 (io), 138 I/O89 B1 (io), 139 I/O90 B2 (io), 140 I/O91 B3 (io), 141 I/O92 B4 (io), 142 I/O93 B5 (io), 143 I/O94 B6 (io), 144 I/O95 B7 (io)
part B pins: 1 GND (power), 2 TDI (in), 11 I2 (in), 12 I3 (in), 13 VCC (power), 14 GND (power), 15 I4 (in), 24 GND (power), 25 VCC (power), 34 TMS (in), 35 TCK (in), 36 GND (power), 37 GND (power), 46 I5 (in), 47 I6 (in), 48 I7 (in), 49 CLK1 (in), 50 GND (power), 51 VCC (power), 52 CLK2 (in), 53 I8 (in), 54 I9 (in), 63 VCC (power), 64 GND (power), 73 GND (power), 74 NC, 83 VCC (power), 84 GND (power), 93 I10 (in), 94 I11 (in), 95 GND (power), 96 VCC (power), 97 I12 (in), 106 NC, 107 TDO (out), 108 GND (power), 109 GND (power), 118 I13 (in), 119 I14 (in), 120 I15 (in), 121 CLK3 (in), 122 VCC (power), 123 GND (power), 124 CLK0 (in), 125 I0 (in), 126 I1 (in), 135 VCC (power), 136 GND (power)

## M4LV-192/96-12VI
designator U?
High-Performance EE CMOS In-System Programmable Logic
footprint TQFP144_N (Thin QFP, 144-Leads, Body 20x20mm, Pitch 0.5mm, IPC Medium Density)
footprint TQFP144_L (Thin QFP, 144-Leads, Body 20x20mm, Pitch 0.5mm, IPC High Density)
footprint TQFP144_M (Thin QFP, 144-Leads, Body 20x20mm, Pitch 0.5mm, IPC Low Density)
3D model M4LV-TQFP144 (144-Pin Thin Quad Flat Pack (TQFP144))
part A pins: 3 I/O0 D7 (io), 4 I/O1 D6 (io), 5 I/O2 D5 (io), 6 I/O3 D4 (io), 7 I/O4 D3 (io), 8 I/O5 D2 (io), 9 I/O6 D1 (io), 10 I/O7 D0 (io), 16 I/O8 C7 (io), 17 I/O9 C6 (io), 18 I/O10 C5 (io), 19 I/O11 C4 (io), 20 I/O12 C3 (io), 21 I/O13 C2 (io), 22 I/O14 C1 (io), 23 I/O15 C0 (io), 26 I/O16 E7 (io), 27 I/O17 E6 (io), 28 I/O18 E5 (io), 29 I/O19 E4 (io), 30 I/O20 E3 (io), 31 I/O21 E2 (io), 32 I/O22 E1 (io), 33 I/O23 E0 (io), 38 I/O24 F7 (io), 39 I/O25 F6 (io), 40 I/O26 F5 (io), 41 I/O27 F4 (io), 42 I/O28 F3 (io), 43 I/O29 F2 (io), 44 I/O30 F1 (io), 45 I/O31 F0 (io), 55 I/O32 G0 (io), 56 I/O33 G1 (io), 57 I/O34 G2 (io), 58 I/O35 G3 (io), 59 I/O36 G4 (io), 60 I/O37 G5 (io), 61 I/O38 G6 (io), 62 I/O39 G7 (io), 65 I/O40 H0 (io), 66 I/O41 H1 (io), 67 I/O42 H2 (io), 68 I/O43 H3 (io), 69 I/O44 H4 (io), 70 I/O45 H5 (io), 71 I/O46 H6 (io), 72 I/O47 H7 (io), 75 I/O48 I7 (io), 76 I/O49 I6 (io), 77 I/O50 I5 (io), 78 I/O51 I4 (io), 79 I/O52 I3 (io), 80 I/O53 I2 (io), 81 I/O54 I1 (io), 82 I/O55 I0 (io), 85 I/O56 J7 (io), 86 I/O57 J6 (io), 87 I/O58 J5 (io), 88 I/O59 J4 (io), 89 I/O60 J3 (io), 90 I/O61 J2 (io), 91 I/O62 J1 (io), 92 I/O63 J0 (io), 98 I/O64 K7 (io), 99 I/O65 K6 (io), 100 I/O66 K5 (io), 101 I/O67 K4 (io), 102 I/O68 K3 (io), 103 I/O69 K2 (io), 104 I/O70 K1 (io), 105 I/O71 K0 (io), 110 I/O72 L7 (io), 111 I/O73 L6 (io), 112 I/O74 L5 (io), 113 I/O75 L4 (io), 114 I/O76 L3 (io), 115 I/O77 L2 (io), 116 I/O78 L1 (io), 117 I/O79 L0 (io), 127 I/O80 A0 (io), 128 I/O81 A1 (io), 129 I/O82 A2 (io), 130 I/O83 A3 (io), 131 I/O84 A4 (io), 132 I/O85 A5 (io), 133 I/O86 A6 (io), 134 I/O87 A7 (io), 137 I/O88 B0 (io), 138 I/O89 B1 (io), 139 I/O90 B2 (io), 140 I/O91 B3 (io), 141 I/O92 B4 (io), 142 I/O93 B5 (io), 143 I/O94 B6 (io), 144 I/O95 B7 (io)
part B pins: 1 GND (power), 2 TDI (in), 11 I2 (in), 12 I3 (in), 13 VCC (power), 14 GND (power), 15 I4 (in), 24 GND (power), 25 VCC (power), 34 TMS (in), 35 TCK (in), 36 GND (power), 37 GND (power), 46 I5 (in), 47 I6 (in), 48 I7 (in), 49 CLK1 (in), 50 GND (power), 51 VCC (power), 52 CLK2 (in), 53 I8 (in), 54 I9 (in), 63 VCC (power), 64 GND (power), 73 GND (power), 74 NC, 83 VCC (power), 84 GND (power), 93 I10 (in), 94 I11 (in), 95 GND (power), 96 VCC (power), 97 I12 (in), 106 NC, 107 TDO (out), 108 GND (power), 109 GND (power), 118 I13 (in), 119 I14 (in), 120 I15 (in), 121 CLK3 (in), 122 VCC (power), 123 GND (power), 124 CLK0 (in), 125 I0 (in), 126 I1 (in), 135 VCC (power), 136 GND (power)

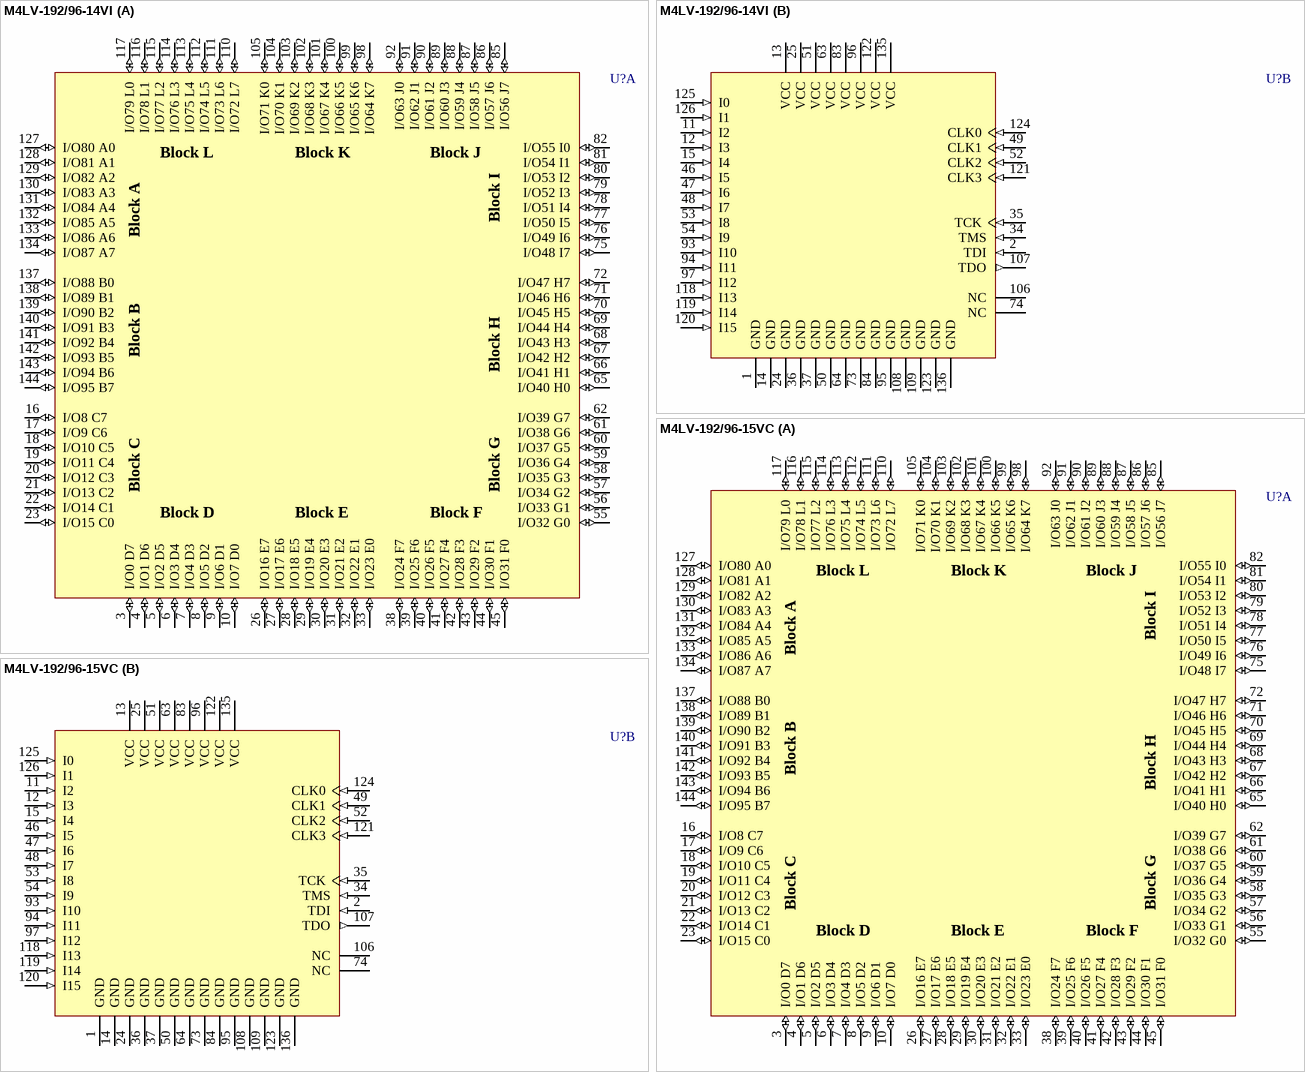
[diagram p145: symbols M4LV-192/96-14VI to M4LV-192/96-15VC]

## M4LV-192/96-14VI
designator U?
High-Performance EE CMOS In-System Programmable Logic
footprint TQFP144_N (Thin QFP, 144-Leads, Body 20x20mm, Pitch 0.5mm, IPC Medium Density)
footprint TQFP144_L (Thin QFP, 144-Leads, Body 20x20mm, Pitch 0.5mm, IPC High Density)
footprint TQFP144_M (Thin QFP, 144-Leads, Body 20x20mm, Pitch 0.5mm, IPC Low Density)
3D model M4LV-TQFP144 (144-Pin Thin Quad Flat Pack (TQFP144))
part A pins: 3 I/O0 D7 (io), 4 I/O1 D6 (io), 5 I/O2 D5 (io), 6 I/O3 D4 (io), 7 I/O4 D3 (io), 8 I/O5 D2 (io), 9 I/O6 D1 (io), 10 I/O7 D0 (io), 16 I/O8 C7 (io), 17 I/O9 C6 (io), 18 I/O10 C5 (io), 19 I/O11 C4 (io), 20 I/O12 C3 (io), 21 I/O13 C2 (io), 22 I/O14 C1 (io), 23 I/O15 C0 (io), 26 I/O16 E7 (io), 27 I/O17 E6 (io), 28 I/O18 E5 (io), 29 I/O19 E4 (io), 30 I/O20 E3 (io), 31 I/O21 E2 (io), 32 I/O22 E1 (io), 33 I/O23 E0 (io), 38 I/O24 F7 (io), 39 I/O25 F6 (io), 40 I/O26 F5 (io), 41 I/O27 F4 (io), 42 I/O28 F3 (io), 43 I/O29 F2 (io), 44 I/O30 F1 (io), 45 I/O31 F0 (io), 55 I/O32 G0 (io), 56 I/O33 G1 (io), 57 I/O34 G2 (io), 58 I/O35 G3 (io), 59 I/O36 G4 (io), 60 I/O37 G5 (io), 61 I/O38 G6 (io), 62 I/O39 G7 (io), 65 I/O40 H0 (io), 66 I/O41 H1 (io), 67 I/O42 H2 (io), 68 I/O43 H3 (io), 69 I/O44 H4 (io), 70 I/O45 H5 (io), 71 I/O46 H6 (io), 72 I/O47 H7 (io), 75 I/O48 I7 (io), 76 I/O49 I6 (io), 77 I/O50 I5 (io), 78 I/O51 I4 (io), 79 I/O52 I3 (io), 80 I/O53 I2 (io), 81 I/O54 I1 (io), 82 I/O55 I0 (io), 85 I/O56 J7 (io), 86 I/O57 J6 (io), 87 I/O58 J5 (io), 88 I/O59 J4 (io), 89 I/O60 J3 (io), 90 I/O61 J2 (io), 91 I/O62 J1 (io), 92 I/O63 J0 (io), 98 I/O64 K7 (io), 99 I/O65 K6 (io), 100 I/O66 K5 (io), 101 I/O67 K4 (io), 102 I/O68 K3 (io), 103 I/O69 K2 (io), 104 I/O70 K1 (io), 105 I/O71 K0 (io), 110 I/O72 L7 (io), 111 I/O73 L6 (io), 112 I/O74 L5 (io), 113 I/O75 L4 (io), 114 I/O76 L3 (io), 115 I/O77 L2 (io), 116 I/O78 L1 (io), 117 I/O79 L0 (io), 127 I/O80 A0 (io), 128 I/O81 A1 (io), 129 I/O82 A2 (io), 130 I/O83 A3 (io), 131 I/O84 A4 (io), 132 I/O85 A5 (io), 133 I/O86 A6 (io), 134 I/O87 A7 (io), 137 I/O88 B0 (io), 138 I/O89 B1 (io), 139 I/O90 B2 (io), 140 I/O91 B3 (io), 141 I/O92 B4 (io), 142 I/O93 B5 (io), 143 I/O94 B6 (io), 144 I/O95 B7 (io)
part B pins: 1 GND (power), 2 TDI (in), 11 I2 (in), 12 I3 (in), 13 VCC (power), 14 GND (power), 15 I4 (in), 24 GND (power), 25 VCC (power), 34 TMS (in), 35 TCK (in), 36 GND (power), 37 GND (power), 46 I5 (in), 47 I6 (in), 48 I7 (in), 49 CLK1 (in), 50 GND (power), 51 VCC (power), 52 CLK2 (in), 53 I8 (in), 54 I9 (in), 63 VCC (power), 64 GND (power), 73 GND (power), 74 NC, 83 VCC (power), 84 GND (power), 93 I10 (in), 94 I11 (in), 95 GND (power), 96 VCC (power), 97 I12 (in), 106 NC, 107 TDO (out), 108 GND (power), 109 GND (power), 118 I13 (in), 119 I14 (in), 120 I15 (in), 121 CLK3 (in), 122 VCC (power), 123 GND (power), 124 CLK0 (in), 125 I0 (in), 126 I1 (in), 135 VCC (power), 136 GND (power)

## M4LV-192/96-15VC
designator U?
High-Performance EE CMOS In-System Programmable Logic
footprint TQFP144_N (Thin QFP, 144-Leads, Body 20x20mm, Pitch 0.5mm, IPC Medium Density)
footprint TQFP144_L (Thin QFP, 144-Leads, Body 20x20mm, Pitch 0.5mm, IPC High Density)
footprint TQFP144_M (Thin QFP, 144-Leads, Body 20x20mm, Pitch 0.5mm, IPC Low Density)
3D model M4LV-TQFP144 (144-Pin Thin Quad Flat Pack (TQFP144))
part A pins: 3 I/O0 D7 (io), 4 I/O1 D6 (io), 5 I/O2 D5 (io), 6 I/O3 D4 (io), 7 I/O4 D3 (io), 8 I/O5 D2 (io), 9 I/O6 D1 (io), 10 I/O7 D0 (io), 16 I/O8 C7 (io), 17 I/O9 C6 (io), 18 I/O10 C5 (io), 19 I/O11 C4 (io), 20 I/O12 C3 (io), 21 I/O13 C2 (io), 22 I/O14 C1 (io), 23 I/O15 C0 (io), 26 I/O16 E7 (io), 27 I/O17 E6 (io), 28 I/O18 E5 (io), 29 I/O19 E4 (io), 30 I/O20 E3 (io), 31 I/O21 E2 (io), 32 I/O22 E1 (io), 33 I/O23 E0 (io), 38 I/O24 F7 (io), 39 I/O25 F6 (io), 40 I/O26 F5 (io), 41 I/O27 F4 (io), 42 I/O28 F3 (io), 43 I/O29 F2 (io), 44 I/O30 F1 (io), 45 I/O31 F0 (io), 55 I/O32 G0 (io), 56 I/O33 G1 (io), 57 I/O34 G2 (io), 58 I/O35 G3 (io), 59 I/O36 G4 (io), 60 I/O37 G5 (io), 61 I/O38 G6 (io), 62 I/O39 G7 (io), 65 I/O40 H0 (io), 66 I/O41 H1 (io), 67 I/O42 H2 (io), 68 I/O43 H3 (io), 69 I/O44 H4 (io), 70 I/O45 H5 (io), 71 I/O46 H6 (io), 72 I/O47 H7 (io), 75 I/O48 I7 (io), 76 I/O49 I6 (io), 77 I/O50 I5 (io), 78 I/O51 I4 (io), 79 I/O52 I3 (io), 80 I/O53 I2 (io), 81 I/O54 I1 (io), 82 I/O55 I0 (io), 85 I/O56 J7 (io), 86 I/O57 J6 (io), 87 I/O58 J5 (io), 88 I/O59 J4 (io), 89 I/O60 J3 (io), 90 I/O61 J2 (io), 91 I/O62 J1 (io), 92 I/O63 J0 (io), 98 I/O64 K7 (io), 99 I/O65 K6 (io), 100 I/O66 K5 (io), 101 I/O67 K4 (io), 102 I/O68 K3 (io), 103 I/O69 K2 (io), 104 I/O70 K1 (io), 105 I/O71 K0 (io), 110 I/O72 L7 (io), 111 I/O73 L6 (io), 112 I/O74 L5 (io), 113 I/O75 L4 (io), 114 I/O76 L3 (io), 115 I/O77 L2 (io), 116 I/O78 L1 (io), 117 I/O79 L0 (io), 127 I/O80 A0 (io), 128 I/O81 A1 (io), 129 I/O82 A2 (io), 130 I/O83 A3 (io), 131 I/O84 A4 (io), 132 I/O85 A5 (io), 133 I/O86 A6 (io), 134 I/O87 A7 (io), 137 I/O88 B0 (io), 138 I/O89 B1 (io), 139 I/O90 B2 (io), 140 I/O91 B3 (io), 141 I/O92 B4 (io), 142 I/O93 B5 (io), 143 I/O94 B6 (io), 144 I/O95 B7 (io)
part B pins: 1 GND (power), 2 TDI (in), 11 I2 (in), 12 I3 (in), 13 VCC (power), 14 GND (power), 15 I4 (in), 24 GND (power), 25 VCC (power), 34 TMS (in), 35 TCK (in), 36 GND (power), 37 GND (power), 46 I5 (in), 47 I6 (in), 48 I7 (in), 49 CLK1 (in), 50 GND (power), 51 VCC (power), 52 CLK2 (in), 53 I8 (in), 54 I9 (in), 63 VCC (power), 64 GND (power), 73 GND (power), 74 NC, 83 VCC (power), 84 GND (power), 93 I10 (in), 94 I11 (in), 95 GND (power), 96 VCC (power), 97 I12 (in), 106 NC, 107 TDO (out), 108 GND (power), 109 GND (power), 118 I13 (in), 119 I14 (in), 120 I15 (in), 121 CLK3 (in), 122 VCC (power), 123 GND (power), 124 CLK0 (in), 125 I0 (in), 126 I1 (in), 135 VCC (power), 136 GND (power)

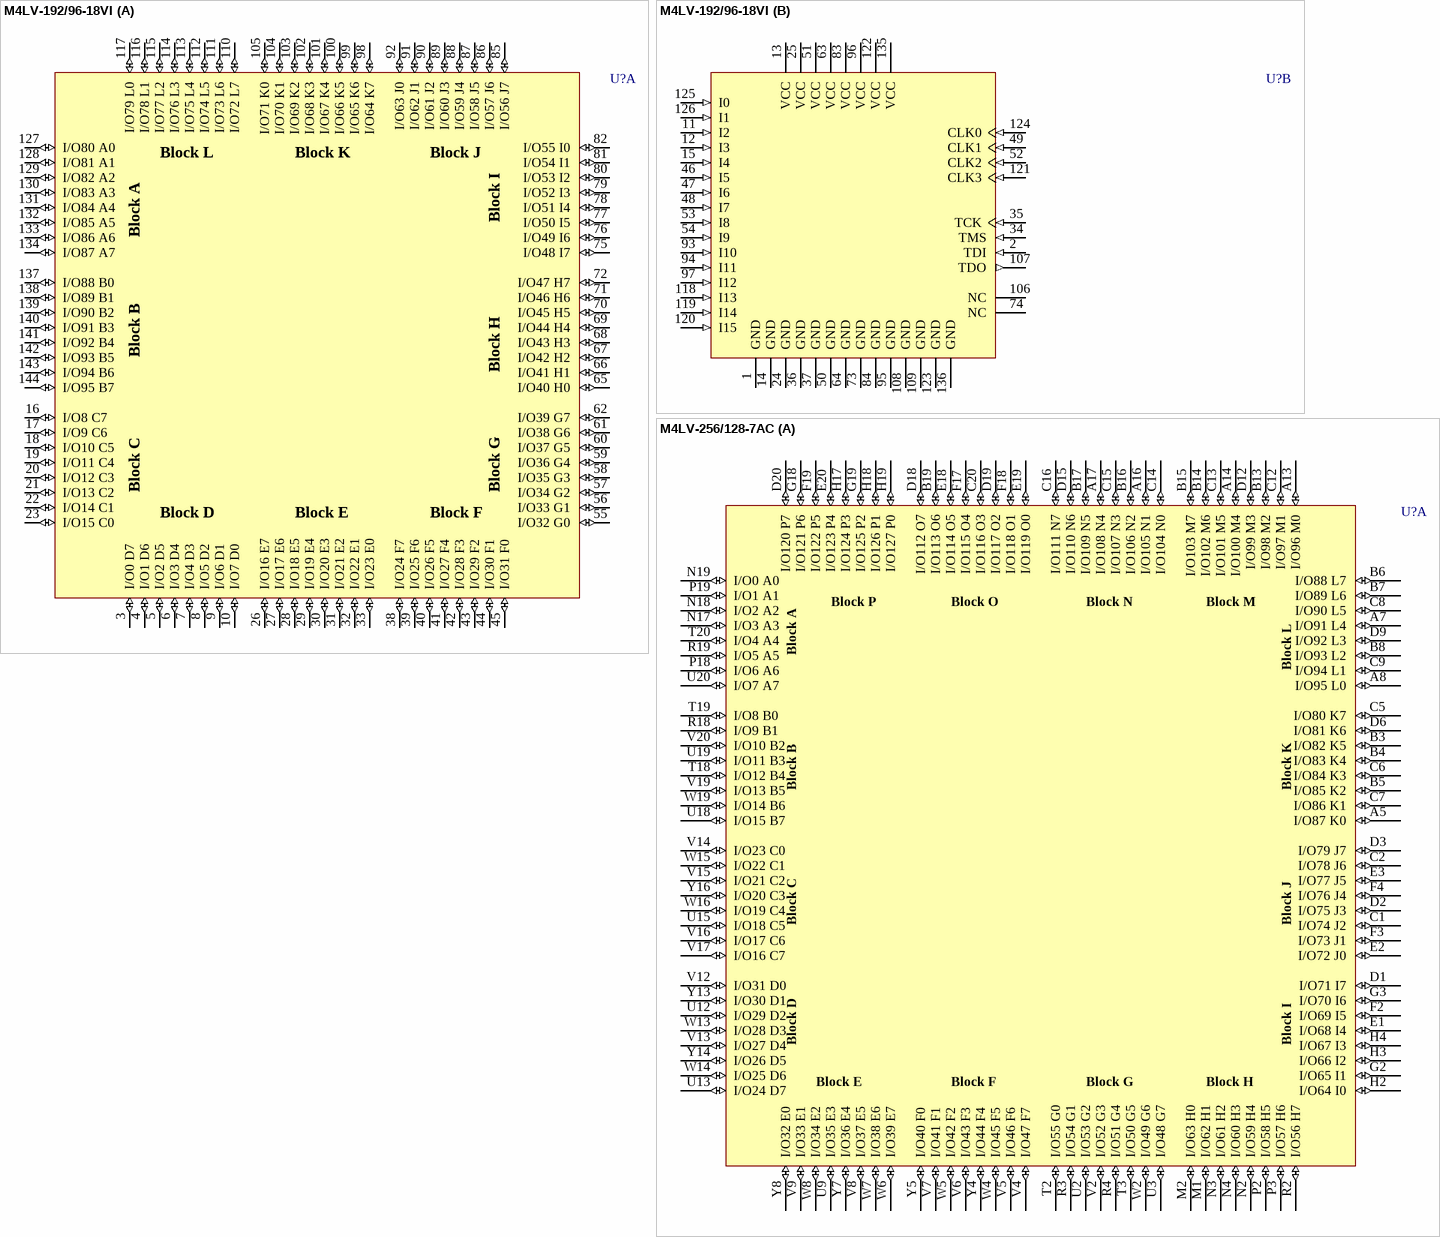
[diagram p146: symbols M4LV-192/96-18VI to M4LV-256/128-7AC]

## M4LV-192/96-18VI
designator U?
High-Performance EE CMOS In-System Programmable Logic
footprint TQFP144_N (Thin QFP, 144-Leads, Body 20x20mm, Pitch 0.5mm, IPC Medium Density)
footprint TQFP144_L (Thin QFP, 144-Leads, Body 20x20mm, Pitch 0.5mm, IPC High Density)
footprint TQFP144_M (Thin QFP, 144-Leads, Body 20x20mm, Pitch 0.5mm, IPC Low Density)
3D model M4LV-TQFP144 (144-Pin Thin Quad Flat Pack (TQFP144))
part A pins: 3 I/O0 D7 (io), 4 I/O1 D6 (io), 5 I/O2 D5 (io), 6 I/O3 D4 (io), 7 I/O4 D3 (io), 8 I/O5 D2 (io), 9 I/O6 D1 (io), 10 I/O7 D0 (io), 16 I/O8 C7 (io), 17 I/O9 C6 (io), 18 I/O10 C5 (io), 19 I/O11 C4 (io), 20 I/O12 C3 (io), 21 I/O13 C2 (io), 22 I/O14 C1 (io), 23 I/O15 C0 (io), 26 I/O16 E7 (io), 27 I/O17 E6 (io), 28 I/O18 E5 (io), 29 I/O19 E4 (io), 30 I/O20 E3 (io), 31 I/O21 E2 (io), 32 I/O22 E1 (io), 33 I/O23 E0 (io), 38 I/O24 F7 (io), 39 I/O25 F6 (io), 40 I/O26 F5 (io), 41 I/O27 F4 (io), 42 I/O28 F3 (io), 43 I/O29 F2 (io), 44 I/O30 F1 (io), 45 I/O31 F0 (io), 55 I/O32 G0 (io), 56 I/O33 G1 (io), 57 I/O34 G2 (io), 58 I/O35 G3 (io), 59 I/O36 G4 (io), 60 I/O37 G5 (io), 61 I/O38 G6 (io), 62 I/O39 G7 (io), 65 I/O40 H0 (io), 66 I/O41 H1 (io), 67 I/O42 H2 (io), 68 I/O43 H3 (io), 69 I/O44 H4 (io), 70 I/O45 H5 (io), 71 I/O46 H6 (io), 72 I/O47 H7 (io), 75 I/O48 I7 (io), 76 I/O49 I6 (io), 77 I/O50 I5 (io), 78 I/O51 I4 (io), 79 I/O52 I3 (io), 80 I/O53 I2 (io), 81 I/O54 I1 (io), 82 I/O55 I0 (io), 85 I/O56 J7 (io), 86 I/O57 J6 (io), 87 I/O58 J5 (io), 88 I/O59 J4 (io), 89 I/O60 J3 (io), 90 I/O61 J2 (io), 91 I/O62 J1 (io), 92 I/O63 J0 (io), 98 I/O64 K7 (io), 99 I/O65 K6 (io), 100 I/O66 K5 (io), 101 I/O67 K4 (io), 102 I/O68 K3 (io), 103 I/O69 K2 (io), 104 I/O70 K1 (io), 105 I/O71 K0 (io), 110 I/O72 L7 (io), 111 I/O73 L6 (io), 112 I/O74 L5 (io), 113 I/O75 L4 (io), 114 I/O76 L3 (io), 115 I/O77 L2 (io), 116 I/O78 L1 (io), 117 I/O79 L0 (io), 127 I/O80 A0 (io), 128 I/O81 A1 (io), 129 I/O82 A2 (io), 130 I/O83 A3 (io), 131 I/O84 A4 (io), 132 I/O85 A5 (io), 133 I/O86 A6 (io), 134 I/O87 A7 (io), 137 I/O88 B0 (io), 138 I/O89 B1 (io), 139 I/O90 B2 (io), 140 I/O91 B3 (io), 141 I/O92 B4 (io), 142 I/O93 B5 (io), 143 I/O94 B6 (io), 144 I/O95 B7 (io)
part B pins: 1 GND (power), 2 TDI (in), 11 I2 (in), 12 I3 (in), 13 VCC (power), 14 GND (power), 15 I4 (in), 24 GND (power), 25 VCC (power), 34 TMS (in), 35 TCK (in), 36 GND (power), 37 GND (power), 46 I5 (in), 47 I6 (in), 48 I7 (in), 49 CLK1 (in), 50 GND (power), 51 VCC (power), 52 CLK2 (in), 53 I8 (in), 54 I9 (in), 63 VCC (power), 64 GND (power), 73 GND (power), 74 NC, 83 VCC (power), 84 GND (power), 93 I10 (in), 94 I11 (in), 95 GND (power), 96 VCC (power), 97 I12 (in), 106 NC, 107 TDO (out), 108 GND (power), 109 GND (power), 118 I13 (in), 119 I14 (in), 120 I15 (in), 121 CLK3 (in), 122 VCC (power), 123 GND (power), 124 CLK0 (in), 125 I0 (in), 126 I1 (in), 135 VCC (power), 136 GND (power)

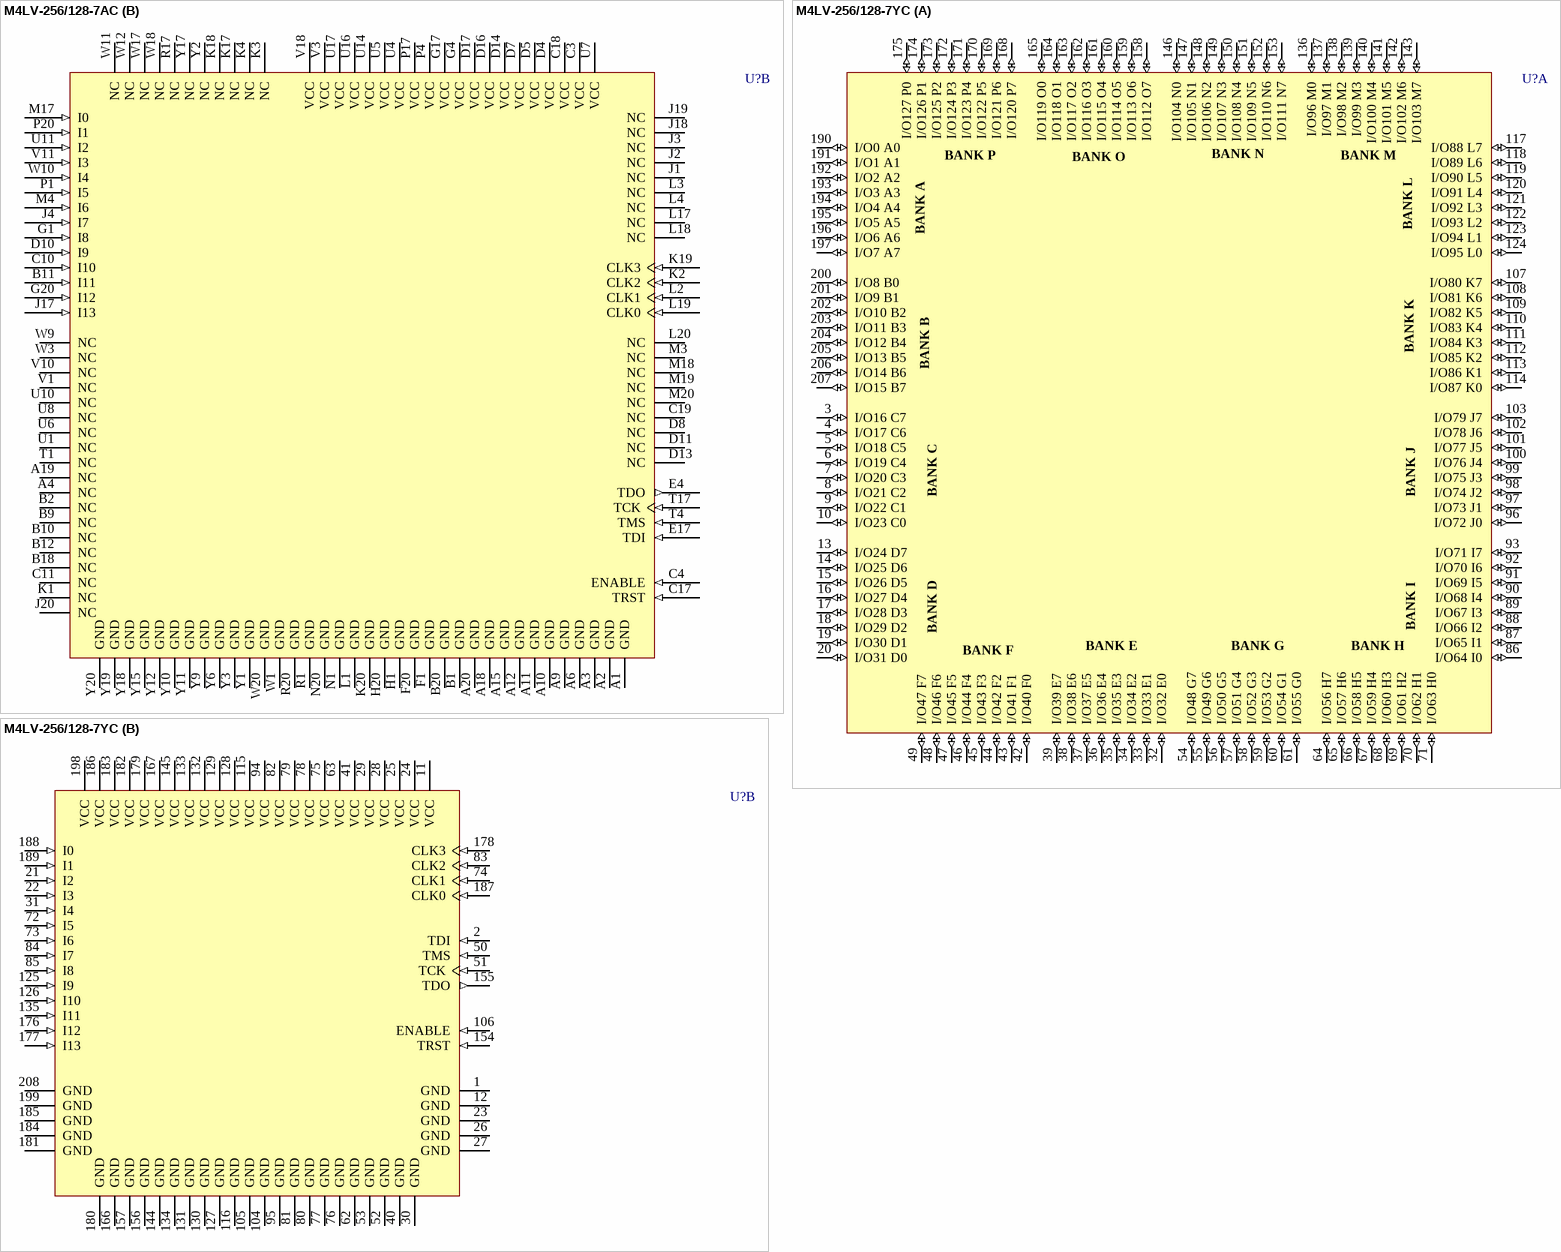
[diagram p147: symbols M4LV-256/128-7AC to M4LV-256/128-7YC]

## M4LV-256/128-7AC
designator U?
High-Performance EE CMOS In-System Programmable Logic
footprint SBGA256 (BGA, 256-Leads, Body 27x27mm, Pitch 1.27mm)
3D model M4LV-SBGA256 (256-Ball Super Ball Grid Array (SBGA256))
part A pins: A5 I/O87 K0 (io), A7 I/O91 L4 (io), A8 I/O95 L0 (io), A13 I/O96 M0 (io), A14 I/O100 M4 (io), A16 I/O105 N1 (io), A17 I/O108 N4 (io), B3 I/O82 K5 (io), B4 I/O83 K4 (io), B5 I/O85 K2 (io), B6 I/O88 L7 (io), B7 I/O89 L6 (io), B8 I/O93 L2 (io), B13 I/O98 M2 (io), B14 I/O102 M6 (io), B15 I/O103 M7 (io), B16 I/O106 N2 (io), B17 I/O109 N5 (io), B19 I/O113 O6 (io), C1 I/O74 J2 (io), C2 I/O78 J6 (io), C5 I/O80 K7 (io), C6 I/O84 K3 (io), C7 I/O86 K1 (io), C8 I/O90 L5 (io), C9 I/O94 L1 (io), C12 I/O97 M1 (io), C13 I/O101 M5 (io), C14 I/O104 N0 (io), C15 I/O107 N3 (io), C16 I/O111 N7 (io), C20 I/O116 O3 (io), D1 I/O71 I7 (io), D2 I/O75 J3 (io), D3 I/O79 J7 (io), D6 I/O81 K6 (io), D9 I/O92 L3 (io), D12 I/O99 M3 (io), D15 I/O110 N6 (io), D18 I/O112 O7 (io), D19 I/O117 O2 (io), D20 I/O120 P7 (io), E1 I/O68 I4 (io), E2 I/O72 J0 (io), E3 I/O77 J5 (io), E18 I/O114 O5 (io), E19 I/O119 O0 (io), E20 I/O123 P4 (io), F2 I/O69 I5 (io), F3 I/O73 J1 (io), F4 I/O76 J4 (io), F17 I/O115 O4 (io), F18 I/O118 O1 (io), F19 I/O122 P5 (io), G2 I/O65 I1 (io), G3 I/O70 I6 (io), G18 I/O121 P6 (io), G19 I/O125 P2 (io), H2 I/O64 I0 (io), H3 I/O66 I2 (io), H4 I/O67 I3 (io), H17 I/O124 P3 (io), H18 I/O126 P1 (io), H19 I/O127 P0 (io), M1 I/O62 H1 (io), M2 I/O63 H0 (io), N2 I/O59 H4 (io), N3 I/O61 H2 (io), N4 I/O60 H3 (io), N17 I/O3 A3 (io), N18 I/O2 A2 (io), N19 I/O0 A0 (io), P2 I/O58 H5 (io), P3 I/O57 H6 (io), P18 I/O6 A6 (io), P19 I/O1 A1 (io), R2 I/O56 H7 (io), R3 I/O54 G1 (io), R4 I/O51 G4 (io), R18 I/O9 B1 (io), R19 I/O5 A5 (io), T2 I/O55 G0 (io), T3 I/O50 G5 (io), T18 I/O12 B4 (io), T19 I/O8 B0 (io), T20 I/O4 A4 (io), U2 I/O53 G2 (io), U3 I/O48 G7 (io), U9 I/O35 E3 (io), U12 I/O29 D2 (io), U13 I/O24 D7 (io), U15 I/O18 C5 (io), U18 I/O15 B7 (io), U19 I/O11 B3 (io), U20 I/O7 A7 (io), V2 I/O52 G3 (io), V4 I/O47 F7 (io), V5 I/O46 F6 (io), V6 I/O43 F3 (io), V7 I/O41 F1 (io), V8 I/O37 E5 (io), V9 I/O33 E1 (io), V12 I/O31 D0 (io), V13 I/O27 D4 (io), V14 I/O23 C0 (io), V15 I/O21 C2 (io), V16 I/O17 C6 (io), V17 I/O16 C7 (io), V19 I/O13 B5 (io), V20 I/O10 B2 (io), W2 I/O49 G6 (io), W4 I/O45 F5 (io), W5 I/O42 F2 (io), W6 I/O39 E7 (io), W7 I/O38 E6 (io), W8 I/O34 E2 (io), W13 I/O28 D3 (io), W14 I/O25 D6 (io), W15 I/O22 C1 (io), W16 I/O19 C4 (io), W19 I/O14 B6 (io), Y4 I/O44 F4 (io), Y5 I/O40 F0 (io), Y7 I/O36 E4 (io), Y8 I/O32 E0 (io), Y13 I/O30 D1 (io), Y14 I/O26 D5 (io), Y16 I/O20 C3 (io)
part B pins: A1 GND (power), A2 GND (power), A3 GND (power), A4 NC, A6 GND (power), A9 GND (power), A10 GND (power), A11 GND (power), A12 GND (power), A15 GND (power), A18 GND (power), A19 NC, A20 GND (power), B1 GND (power), B2 NC, B9 NC, B10 NC, B11 I11 (in), B12 NC, B18 NC, B20 GND (power), C3 VCC (power), C4 ENABLE (in), C10 I10 (in), C11 NC, C17 TRST (in), C18 VCC (power), C19 NC, D4 VCC (power), D5 VCC (power), D7 VCC (power), D8 NC, D10 I9 (in), D11 NC, D13 NC, D14 VCC (power), D16 VCC (power), D17 VCC (power), E4 TDO (out), E17 TDI (in), F1 GND (power), F20 GND (power), G1 I8 (in), G4 VCC (power), G17 VCC (power), G20 I12 (in), H1 GND (power), H20 GND (power), J1 NC, J2 NC, J3 NC, J4 I7 (in), J17 I13 (in), J18 NC, J19 NC, J20 NC, K1 NC, K2 CLK2 (in), K3 NC, K4 NC, K17 NC, K18 NC, K19 CLK3 (in), K20 GND (power), L1 GND (power), L2 CLK1 (in), L3 NC, L4 NC, L17 NC, L18 NC, L19 CLK0 (in), L20 NC, M3 NC, M4 I6 (in), M17 I0 (in), M18 NC, M19 NC, M20 NC, N1 GND (power), N20 GND (power), P1 I5 (in), P4 VCC (power), P17 VCC (power), P20 I1 (in), R1 GND (power), R17 NC, R20 GND (power), T1 NC, T4 TMS (in), T17 TCK (in), U1 NC, U4 VCC (power), U5 VCC (power), U6 NC, U7 VCC (power), U8 NC, U10 NC, U11 I2 (in), U14 VCC (power), U16 VCC (power), U17 VCC (power), V1 NC, V3 VCC (power), V10 NC, V11 I3 (in), V18 VCC (power), W1 GND (power), W3 NC, W9 NC, W10 I4 (in), W11 NC, W12 NC, W17 NC, W18 NC, W20 GND (power), Y1 GND (power), Y2 NC, Y3 GND (power), Y6 GND (power), Y9 GND (power), Y10 GND (power), Y11 GND (power), Y12 GND (power), Y15 GND (power), Y17 NC, Y18 GND (power), Y19 GND (power), Y20 GND (power)

## M4LV-256/128-7YC
designator U?
High-Performance EE CMOS In-System Programmable Logic
footprint PQFP208_N (Shrink QFP, 208-Leads, Body 28x28mm, Pitch 0.5mm, IPC Medium Density)
footprint PQFP208_L (Shrink QFP, 208-Leads, Body 28x28mm, Pitch 0.5mm, IPC High Density)
footprint PQFP208_M (Shrink QFP, 208-Leads, Body 28x28mm, Pitch 0.5mm, IPC Low Density)
3D model M4LV-PQFP208 (208-Pin Plastic Quad Flat Pack (PQFP208))
part A pins: 3 I/O16 C7 (io), 4 I/O17 C6 (io), 5 I/O18 C5 (io), 6 I/O19 C4 (io), 7 I/O20 C3 (io), 8 I/O21 C2 (io), 9 I/O22 C1 (io), 10 I/O23 C0 (io), 13 I/O24 D7 (io), 14 I/O25 D6 (io), 15 I/O26 D5 (io), 16 I/O27 D4 (io), 17 I/O28 D3 (io), 18 I/O29 D2 (io), 19 I/O30 D1 (io), 20 I/O31 D0 (io), 32 I/O32 E0 (io), 33 I/O33 E1 (io), 34 I/O34 E2 (io), 35 I/O35 E3 (io), 36 I/O36 E4 (io), 37 I/O37 E5 (io), 38 I/O38 E6 (io), 39 I/O39 E7 (io), 42 I/O40 F0 (io), 43 I/O41 F1 (io), 44 I/O42 F2 (io), 45 I/O43 F3 (io), 46 I/O44 F4 (io), 47 I/O45 F5 (io), 48 I/O46 F6 (io), 49 I/O47 F7 (io), 54 I/O48 G7 (io), 55 I/O49 G6 (io), 56 I/O50 G5 (io), 57 I/O51 G4 (io), 58 I/O52 G3 (io), 59 I/O53 G2 (io), 60 I/O54 G1 (io), 61 I/O55 G0 (io), 64 I/O56 H7 (io), 65 I/O57 H6 (io), 66 I/O58 H5 (io), 67 I/O59 H4 (io), 68 I/O60 H3 (io), 69 I/O61 H2 (io), 70 I/O62 H1 (io), 71 I/O63 H0 (io), 86 I/O64 I0 (io), 87 I/O65 I1 (io), 88 I/O66 I2 (io), 89 I/O67 I3 (io), 90 I/O68 I4 (io), 91 I/O69 I5 (io), 92 I/O70 I6 (io), 93 I/O71 I7 (io), 96 I/O72 J0 (io), 97 I/O73 J1 (io), 98 I/O74 J2 (io), 99 I/O75 J3 (io), 100 I/O76 J4 (io), 101 I/O77 J5 (io), 102 I/O78 J6 (io), 103 I/O79 J7 (io), 107 I/O80 K7 (io), 108 I/O81 K6 (io), 109 I/O82 K5 (io), 110 I/O83 K4 (io), 111 I/O84 K3 (io), 112 I/O85 K2 (io), 113 I/O86 K1 (io), 114 I/O87 K0 (io), 117 I/O88 L7 (io), 118 I/O89 L6 (io), 119 I/O90 L5 (io), 120 I/O91 L4 (io), 121 I/O92 L3 (io), 122 I/O93 L2 (io), 123 I/O94 L1 (io), 124 I/O95 L0 (io), 136 I/O96 M0 (io), 137 I/O97 M1 (io), 138 I/O98 M2 (io), 139 I/O99 M3 (io), 140 I/O100 M4 (io), 141 I/O101 M5 (io), 142 I/O102 M6 (io), 143 I/O103 M7 (io), 146 I/O104 N0 (io), 147 I/O105 N1 (io), 148 I/O106 N2 (io), 149 I/O107 N3 (io), 150 I/O108 N4 (io), 151 I/O109 N5 (io), 152 I/O110 N6 (io), 153 I/O111 N7 (io), 158 I/O112 O7 (io), 159 I/O113 O6 (io), 160 I/O114 O5 (io), 161 I/O115 O4 (io), 162 I/O116 O3 (io), 163 I/O117 O2 (io), 164 I/O118 O1 (io), 165 I/O119 O0 (io), 168 I/O120 P7 (io), 169 I/O121 P6 (io), 170 I/O122 P5 (io), 171 I/O123 P4 (io), 172 I/O124 P3 (io), 173 I/O125 P2 (io), 174 I/O126 P1 (io), 175 I/O127 P0 (io), 190 I/O0 A0 (io), 191 I/O1 A1 (io), 192 I/O2 A2 (io), 193 I/O3 A3 (io), 194 I/O4 A4 (io), 195 I/O5 A5 (io), 196 I/O6 A6 (io), 197 I/O7 A7 (io), 200 I/O8 B0 (io), 201 I/O9 B1 (io), 202 I/O10 B2 (io), 203 I/O11 B3 (io), 204 I/O12 B4 (io), 205 I/O13 B5 (io), 206 I/O14 B6 (io), 207 I/O15 B7 (io)
part B pins: 1 GND (power), 2 TDI (in), 11 VCC (power), 12 GND (power), 21 I2 (in), 22 I3 (in), 23 GND (power), 24 VCC (power), 25 VCC (power), 26 GND (power), 27 GND (power), 28 VCC (power), 29 VCC (power), 30 GND (power), 31 I4 (in), 40 GND (power), 41 VCC (power), 50 TMS (in), 51 TCK (in), 52 GND (power), 53 GND (power), 62 GND (power), 63 VCC (power), 72 I5 (in), 73 I6 (in), 74 CLK1 (in), 75 VCC (power), 76 GND (power), 77 GND (power), 78 VCC (power), 79 VCC (power), 80 GND (power), 81 GND (power), 82 VCC (power), 83 CLK2 (in), 84 I7 (in), 85 I8 (in), 94 VCC (power), 95 GND (power), 104 GND (power), 105 GND (power), 106 ENABLE (in), 115 VCC (power), 116 GND (power), 125 I9 (in), 126 I10 (in), 127 GND (power), 128 VCC (power), 129 VCC (power), 130 GND (power), 131 GND (power), 132 VCC (power), 133 VCC (power), 134 GND (power), 135 I11 (in), 144 GND (power), 145 VCC (power), 154 TRST (in), 155 TDO (out), 156 GND (power), 157 GND (power), 166 GND (power), 167 VCC (power), 176 I12 (in), 177 I13 (in), 178 CLK3 (in), 179 VCC (power), 180 GND (power), 181 GND (power), 182 VCC (power), 183 VCC (power), 184 GND (power), 185 GND (power), 186 VCC (power), 187 CLK0 (in), 188 I0 (in), 189 I1 (in), 198 VCC (power), 199 GND (power), 208 GND (power)

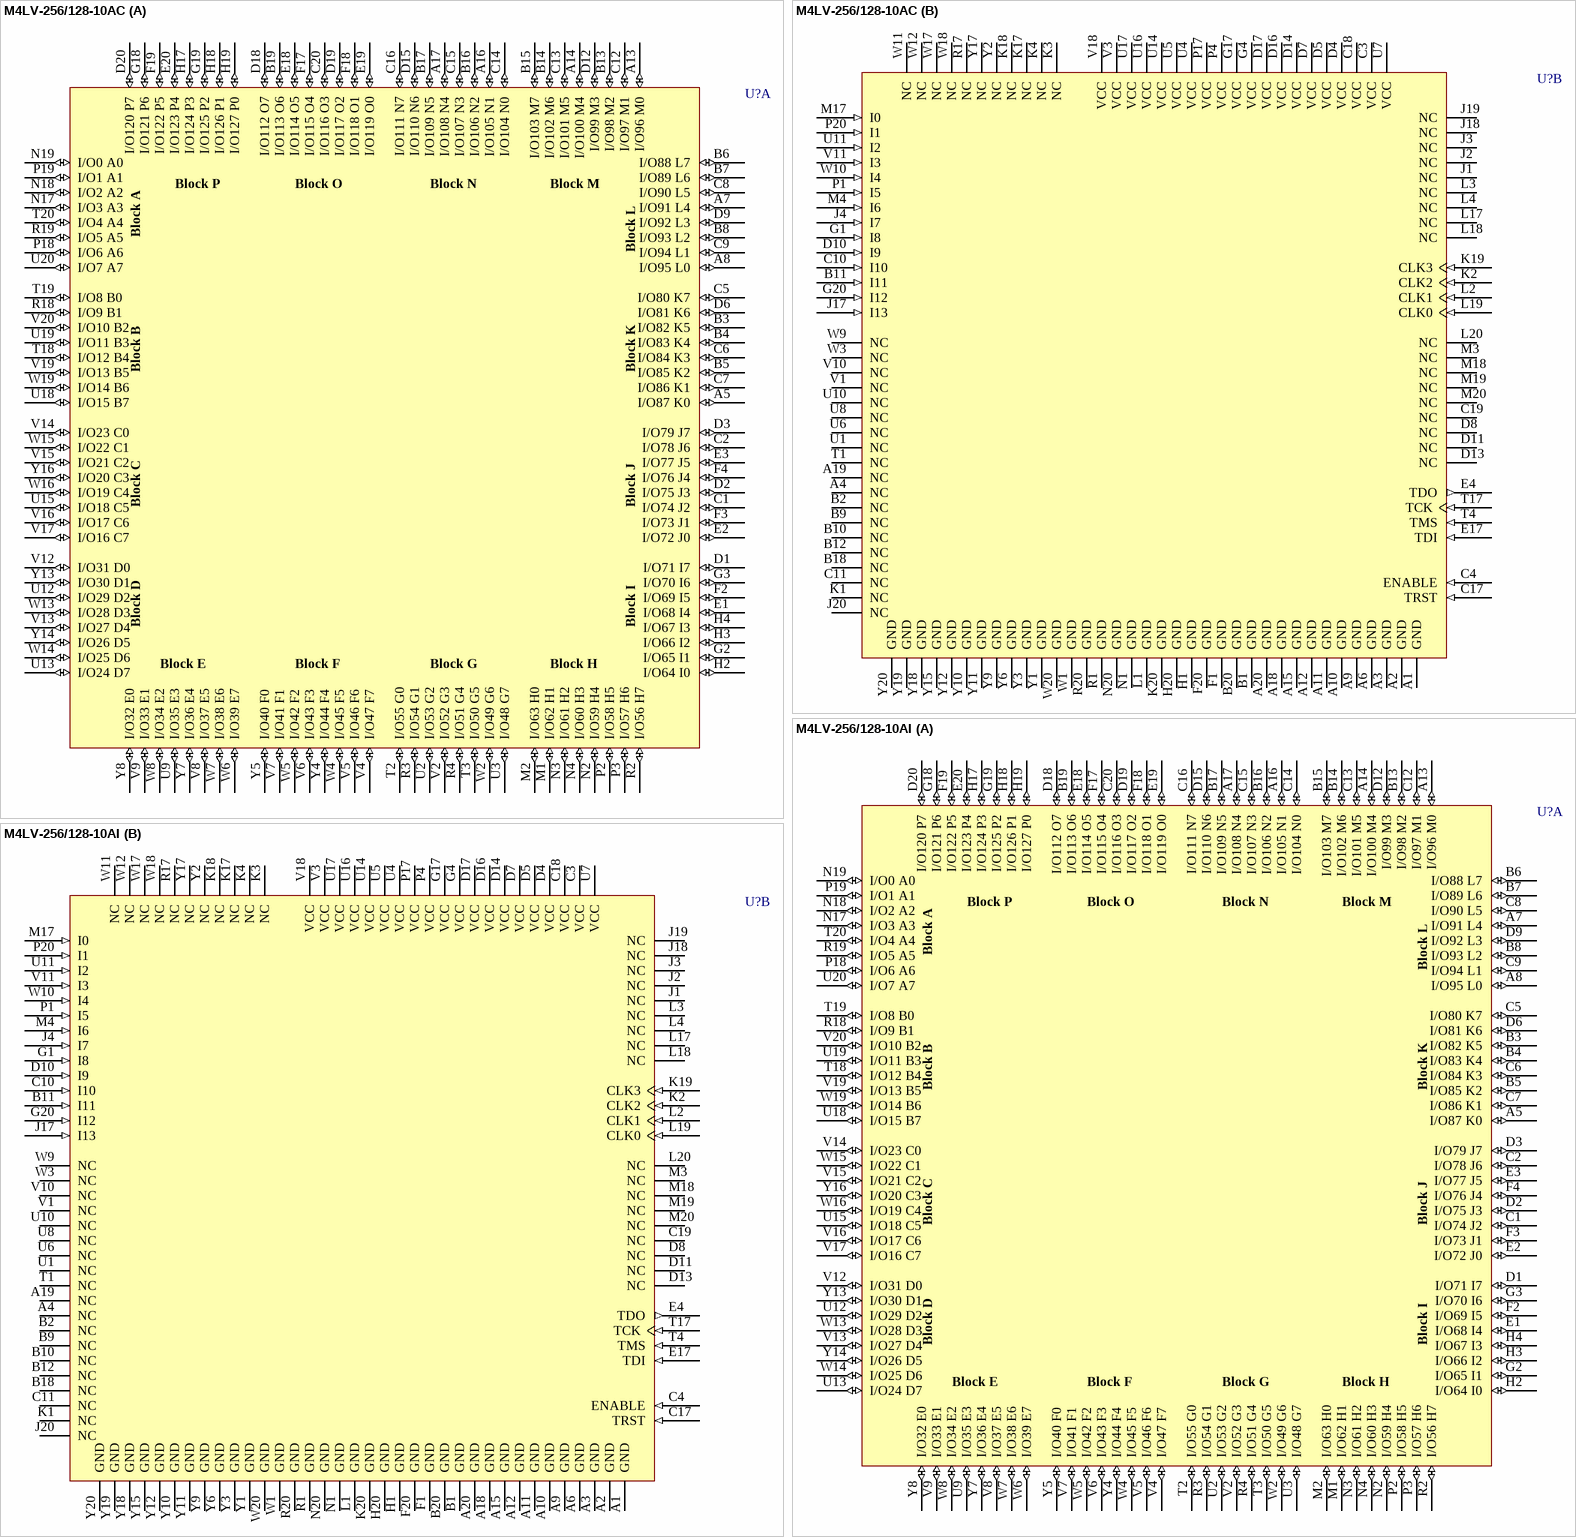
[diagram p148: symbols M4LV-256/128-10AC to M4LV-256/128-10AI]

## M4LV-256/128-10AC
designator U?
High-Performance EE CMOS In-System Programmable Logic
footprint SBGA256 (BGA, 256-Leads, Body 27x27mm, Pitch 1.27mm)
3D model M4LV-SBGA256 (256-Ball Super Ball Grid Array (SBGA256))
part A pins: A5 I/O87 K0 (io), A7 I/O91 L4 (io), A8 I/O95 L0 (io), A13 I/O96 M0 (io), A14 I/O100 M4 (io), A16 I/O105 N1 (io), A17 I/O108 N4 (io), B3 I/O82 K5 (io), B4 I/O83 K4 (io), B5 I/O85 K2 (io), B6 I/O88 L7 (io), B7 I/O89 L6 (io), B8 I/O93 L2 (io), B13 I/O98 M2 (io), B14 I/O102 M6 (io), B15 I/O103 M7 (io), B16 I/O106 N2 (io), B17 I/O109 N5 (io), B19 I/O113 O6 (io), C1 I/O74 J2 (io), C2 I/O78 J6 (io), C5 I/O80 K7 (io), C6 I/O84 K3 (io), C7 I/O86 K1 (io), C8 I/O90 L5 (io), C9 I/O94 L1 (io), C12 I/O97 M1 (io), C13 I/O101 M5 (io), C14 I/O104 N0 (io), C15 I/O107 N3 (io), C16 I/O111 N7 (io), C20 I/O116 O3 (io), D1 I/O71 I7 (io), D2 I/O75 J3 (io), D3 I/O79 J7 (io), D6 I/O81 K6 (io), D9 I/O92 L3 (io), D12 I/O99 M3 (io), D15 I/O110 N6 (io), D18 I/O112 O7 (io), D19 I/O117 O2 (io), D20 I/O120 P7 (io), E1 I/O68 I4 (io), E2 I/O72 J0 (io), E3 I/O77 J5 (io), E18 I/O114 O5 (io), E19 I/O119 O0 (io), E20 I/O123 P4 (io), F2 I/O69 I5 (io), F3 I/O73 J1 (io), F4 I/O76 J4 (io), F17 I/O115 O4 (io), F18 I/O118 O1 (io), F19 I/O122 P5 (io), G2 I/O65 I1 (io), G3 I/O70 I6 (io), G18 I/O121 P6 (io), G19 I/O125 P2 (io), H2 I/O64 I0 (io), H3 I/O66 I2 (io), H4 I/O67 I3 (io), H17 I/O124 P3 (io), H18 I/O126 P1 (io), H19 I/O127 P0 (io), M1 I/O62 H1 (io), M2 I/O63 H0 (io), N2 I/O59 H4 (io), N3 I/O61 H2 (io), N4 I/O60 H3 (io), N17 I/O3 A3 (io), N18 I/O2 A2 (io), N19 I/O0 A0 (io), P2 I/O58 H5 (io), P3 I/O57 H6 (io), P18 I/O6 A6 (io), P19 I/O1 A1 (io), R2 I/O56 H7 (io), R3 I/O54 G1 (io), R4 I/O51 G4 (io), R18 I/O9 B1 (io), R19 I/O5 A5 (io), T2 I/O55 G0 (io), T3 I/O50 G5 (io), T18 I/O12 B4 (io), T19 I/O8 B0 (io), T20 I/O4 A4 (io), U2 I/O53 G2 (io), U3 I/O48 G7 (io), U9 I/O35 E3 (io), U12 I/O29 D2 (io), U13 I/O24 D7 (io), U15 I/O18 C5 (io), U18 I/O15 B7 (io), U19 I/O11 B3 (io), U20 I/O7 A7 (io), V2 I/O52 G3 (io), V4 I/O47 F7 (io), V5 I/O46 F6 (io), V6 I/O43 F3 (io), V7 I/O41 F1 (io), V8 I/O37 E5 (io), V9 I/O33 E1 (io), V12 I/O31 D0 (io), V13 I/O27 D4 (io), V14 I/O23 C0 (io), V15 I/O21 C2 (io), V16 I/O17 C6 (io), V17 I/O16 C7 (io), V19 I/O13 B5 (io), V20 I/O10 B2 (io), W2 I/O49 G6 (io), W4 I/O45 F5 (io), W5 I/O42 F2 (io), W6 I/O39 E7 (io), W7 I/O38 E6 (io), W8 I/O34 E2 (io), W13 I/O28 D3 (io), W14 I/O25 D6 (io), W15 I/O22 C1 (io), W16 I/O19 C4 (io), W19 I/O14 B6 (io), Y4 I/O44 F4 (io), Y5 I/O40 F0 (io), Y7 I/O36 E4 (io), Y8 I/O32 E0 (io), Y13 I/O30 D1 (io), Y14 I/O26 D5 (io), Y16 I/O20 C3 (io)
part B pins: A1 GND (power), A2 GND (power), A3 GND (power), A4 NC, A6 GND (power), A9 GND (power), A10 GND (power), A11 GND (power), A12 GND (power), A15 GND (power), A18 GND (power), A19 NC, A20 GND (power), B1 GND (power), B2 NC, B9 NC, B10 NC, B11 I11 (in), B12 NC, B18 NC, B20 GND (power), C3 VCC (power), C4 ENABLE (in), C10 I10 (in), C11 NC, C17 TRST (in), C18 VCC (power), C19 NC, D4 VCC (power), D5 VCC (power), D7 VCC (power), D8 NC, D10 I9 (in), D11 NC, D13 NC, D14 VCC (power), D16 VCC (power), D17 VCC (power), E4 TDO (out), E17 TDI (in), F1 GND (power), F20 GND (power), G1 I8 (in), G4 VCC (power), G17 VCC (power), G20 I12 (in), H1 GND (power), H20 GND (power), J1 NC, J2 NC, J3 NC, J4 I7 (in), J17 I13 (in), J18 NC, J19 NC, J20 NC, K1 NC, K2 CLK2 (in), K3 NC, K4 NC, K17 NC, K18 NC, K19 CLK3 (in), K20 GND (power), L1 GND (power), L2 CLK1 (in), L3 NC, L4 NC, L17 NC, L18 NC, L19 CLK0 (in), L20 NC, M3 NC, M4 I6 (in), M17 I0 (in), M18 NC, M19 NC, M20 NC, N1 GND (power), N20 GND (power), P1 I5 (in), P4 VCC (power), P17 VCC (power), P20 I1 (in), R1 GND (power), R17 NC, R20 GND (power), T1 NC, T4 TMS (in), T17 TCK (in), U1 NC, U4 VCC (power), U5 VCC (power), U6 NC, U7 VCC (power), U8 NC, U10 NC, U11 I2 (in), U14 VCC (power), U16 VCC (power), U17 VCC (power), V1 NC, V3 VCC (power), V10 NC, V11 I3 (in), V18 VCC (power), W1 GND (power), W3 NC, W9 NC, W10 I4 (in), W11 NC, W12 NC, W17 NC, W18 NC, W20 GND (power), Y1 GND (power), Y2 NC, Y3 GND (power), Y6 GND (power), Y9 GND (power), Y10 GND (power), Y11 GND (power), Y12 GND (power), Y15 GND (power), Y17 NC, Y18 GND (power), Y19 GND (power), Y20 GND (power)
